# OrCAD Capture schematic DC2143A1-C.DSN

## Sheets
1 PAGE1: size C
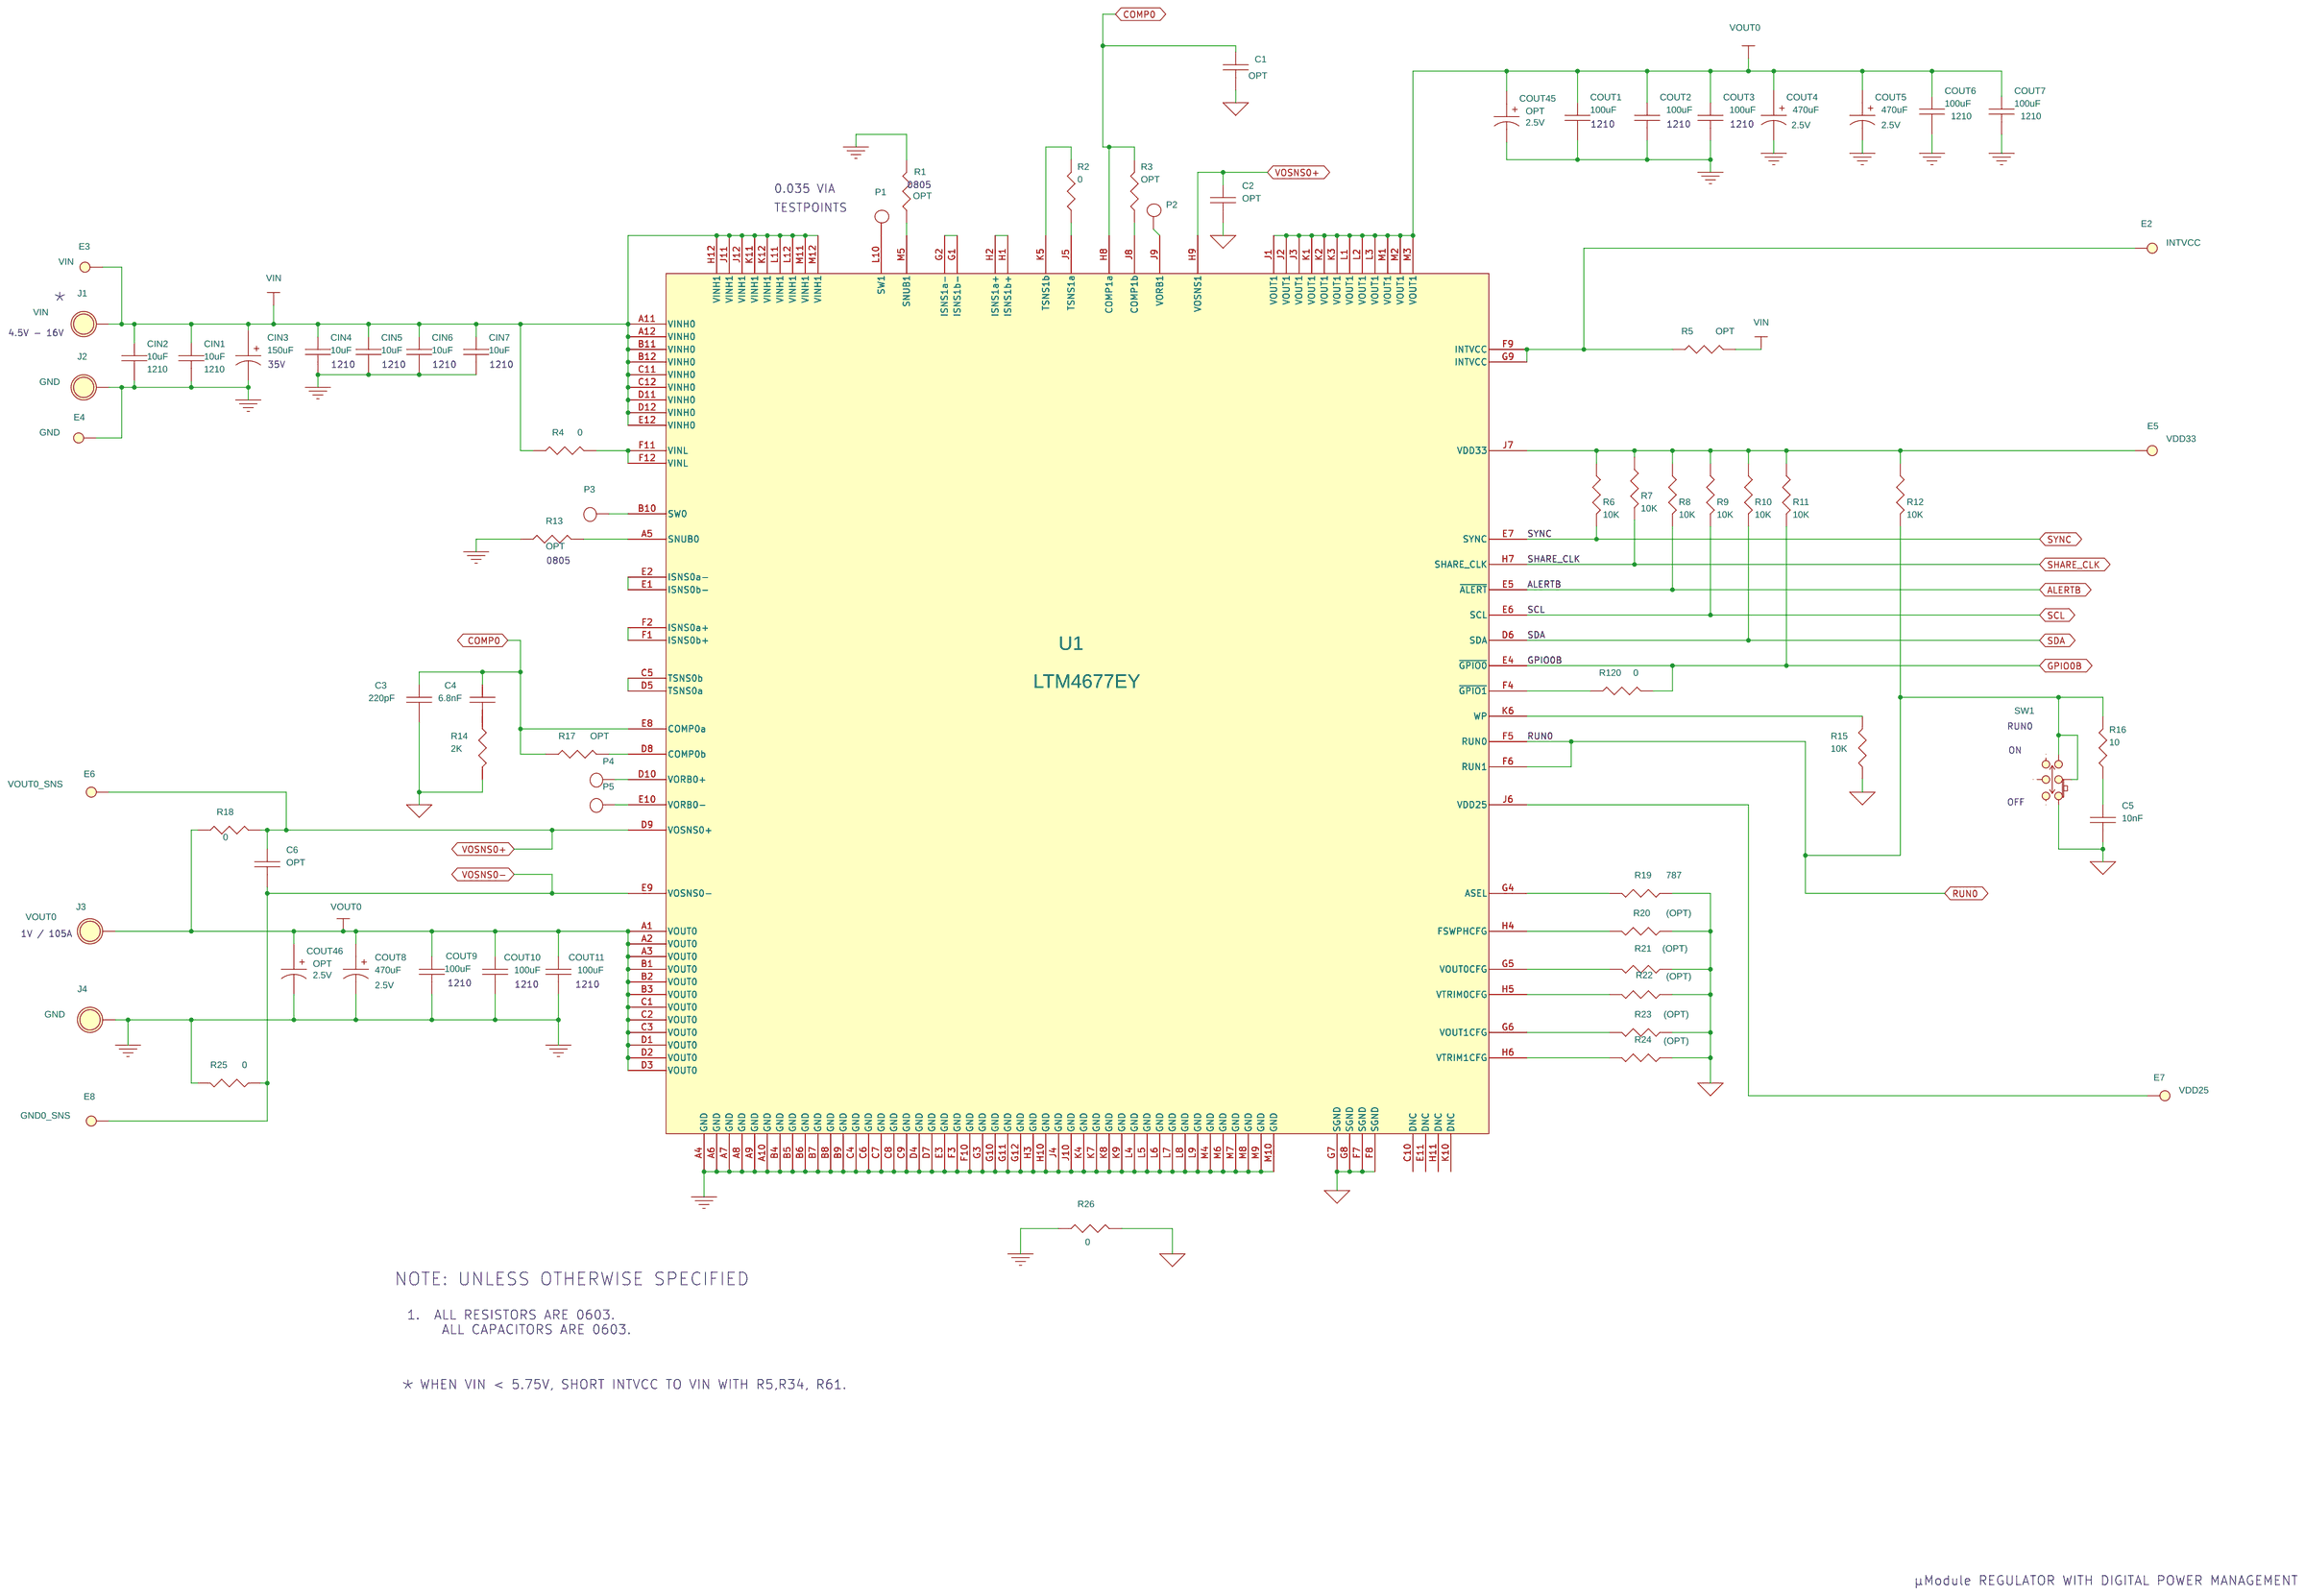
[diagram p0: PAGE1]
2 PAGE2: size C; title: HIGH EFFICIENCY, POLY-PHASE, DC/DC STEP-DOWN; rev: 1; company: TM
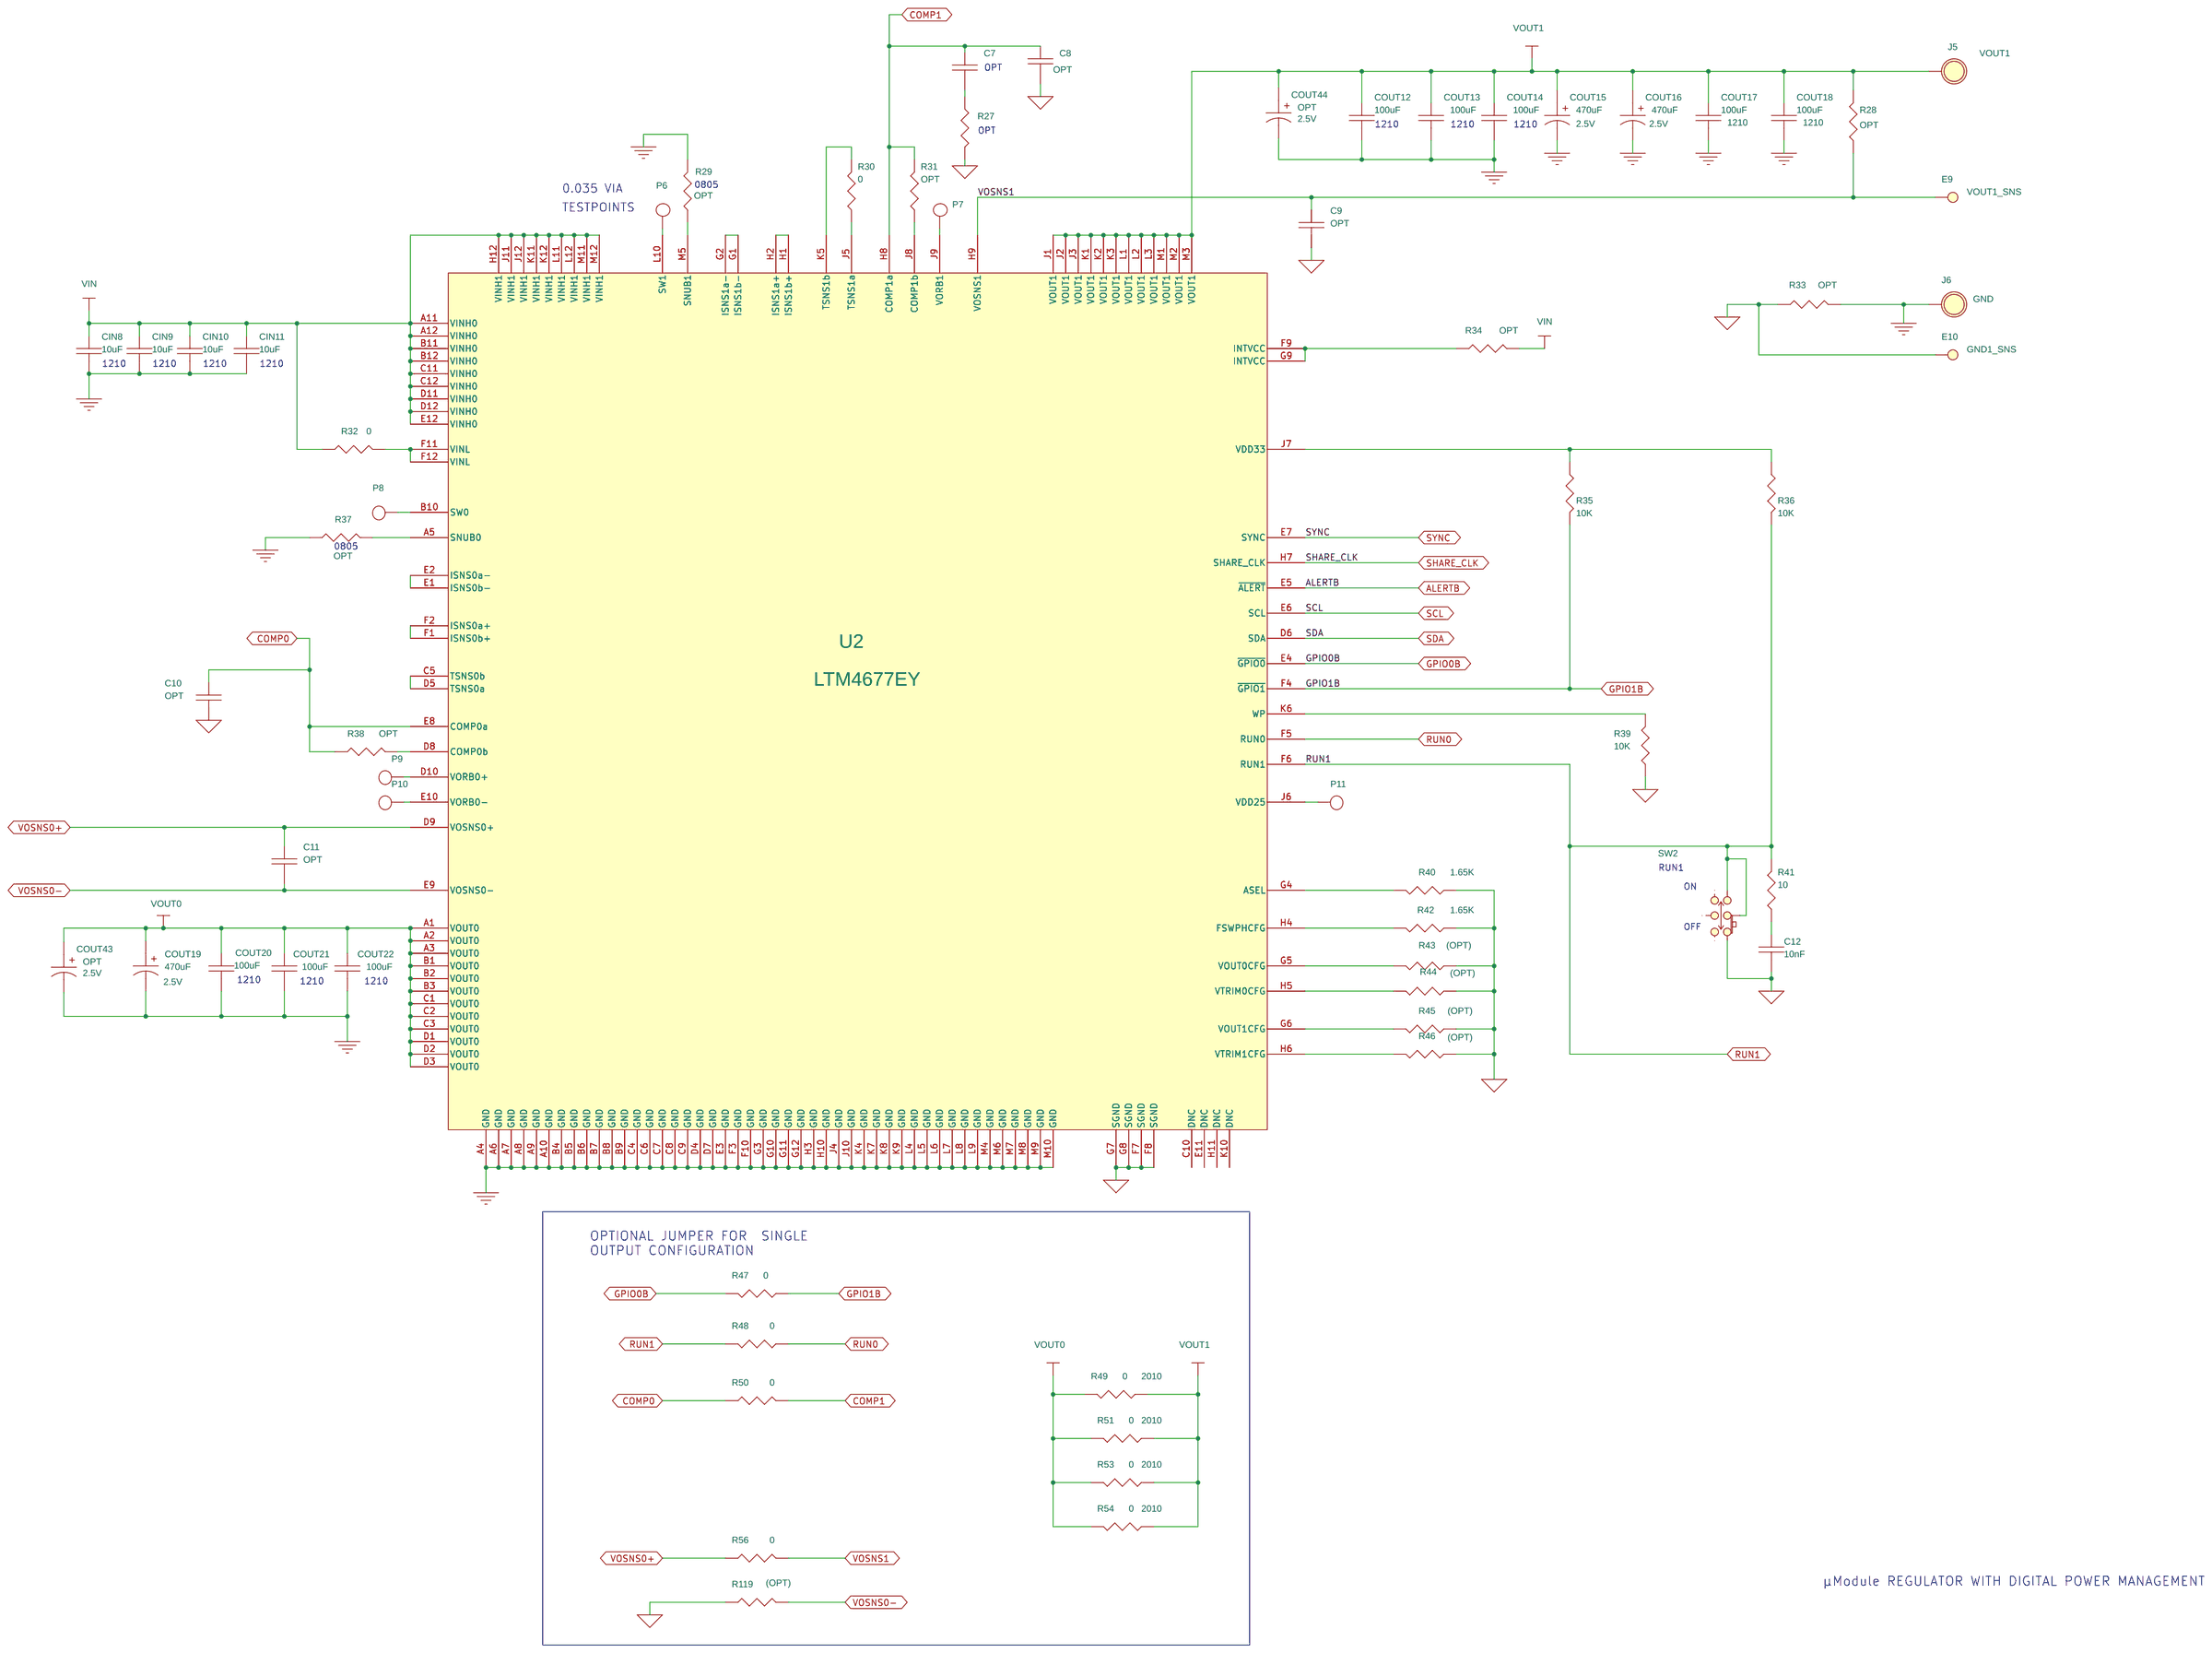
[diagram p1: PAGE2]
3 PAGE3: size C; title: HIGH EFFICIENCY, POLY-PHASE, DC/DC STEP-DOWN; rev: 1; company: TM
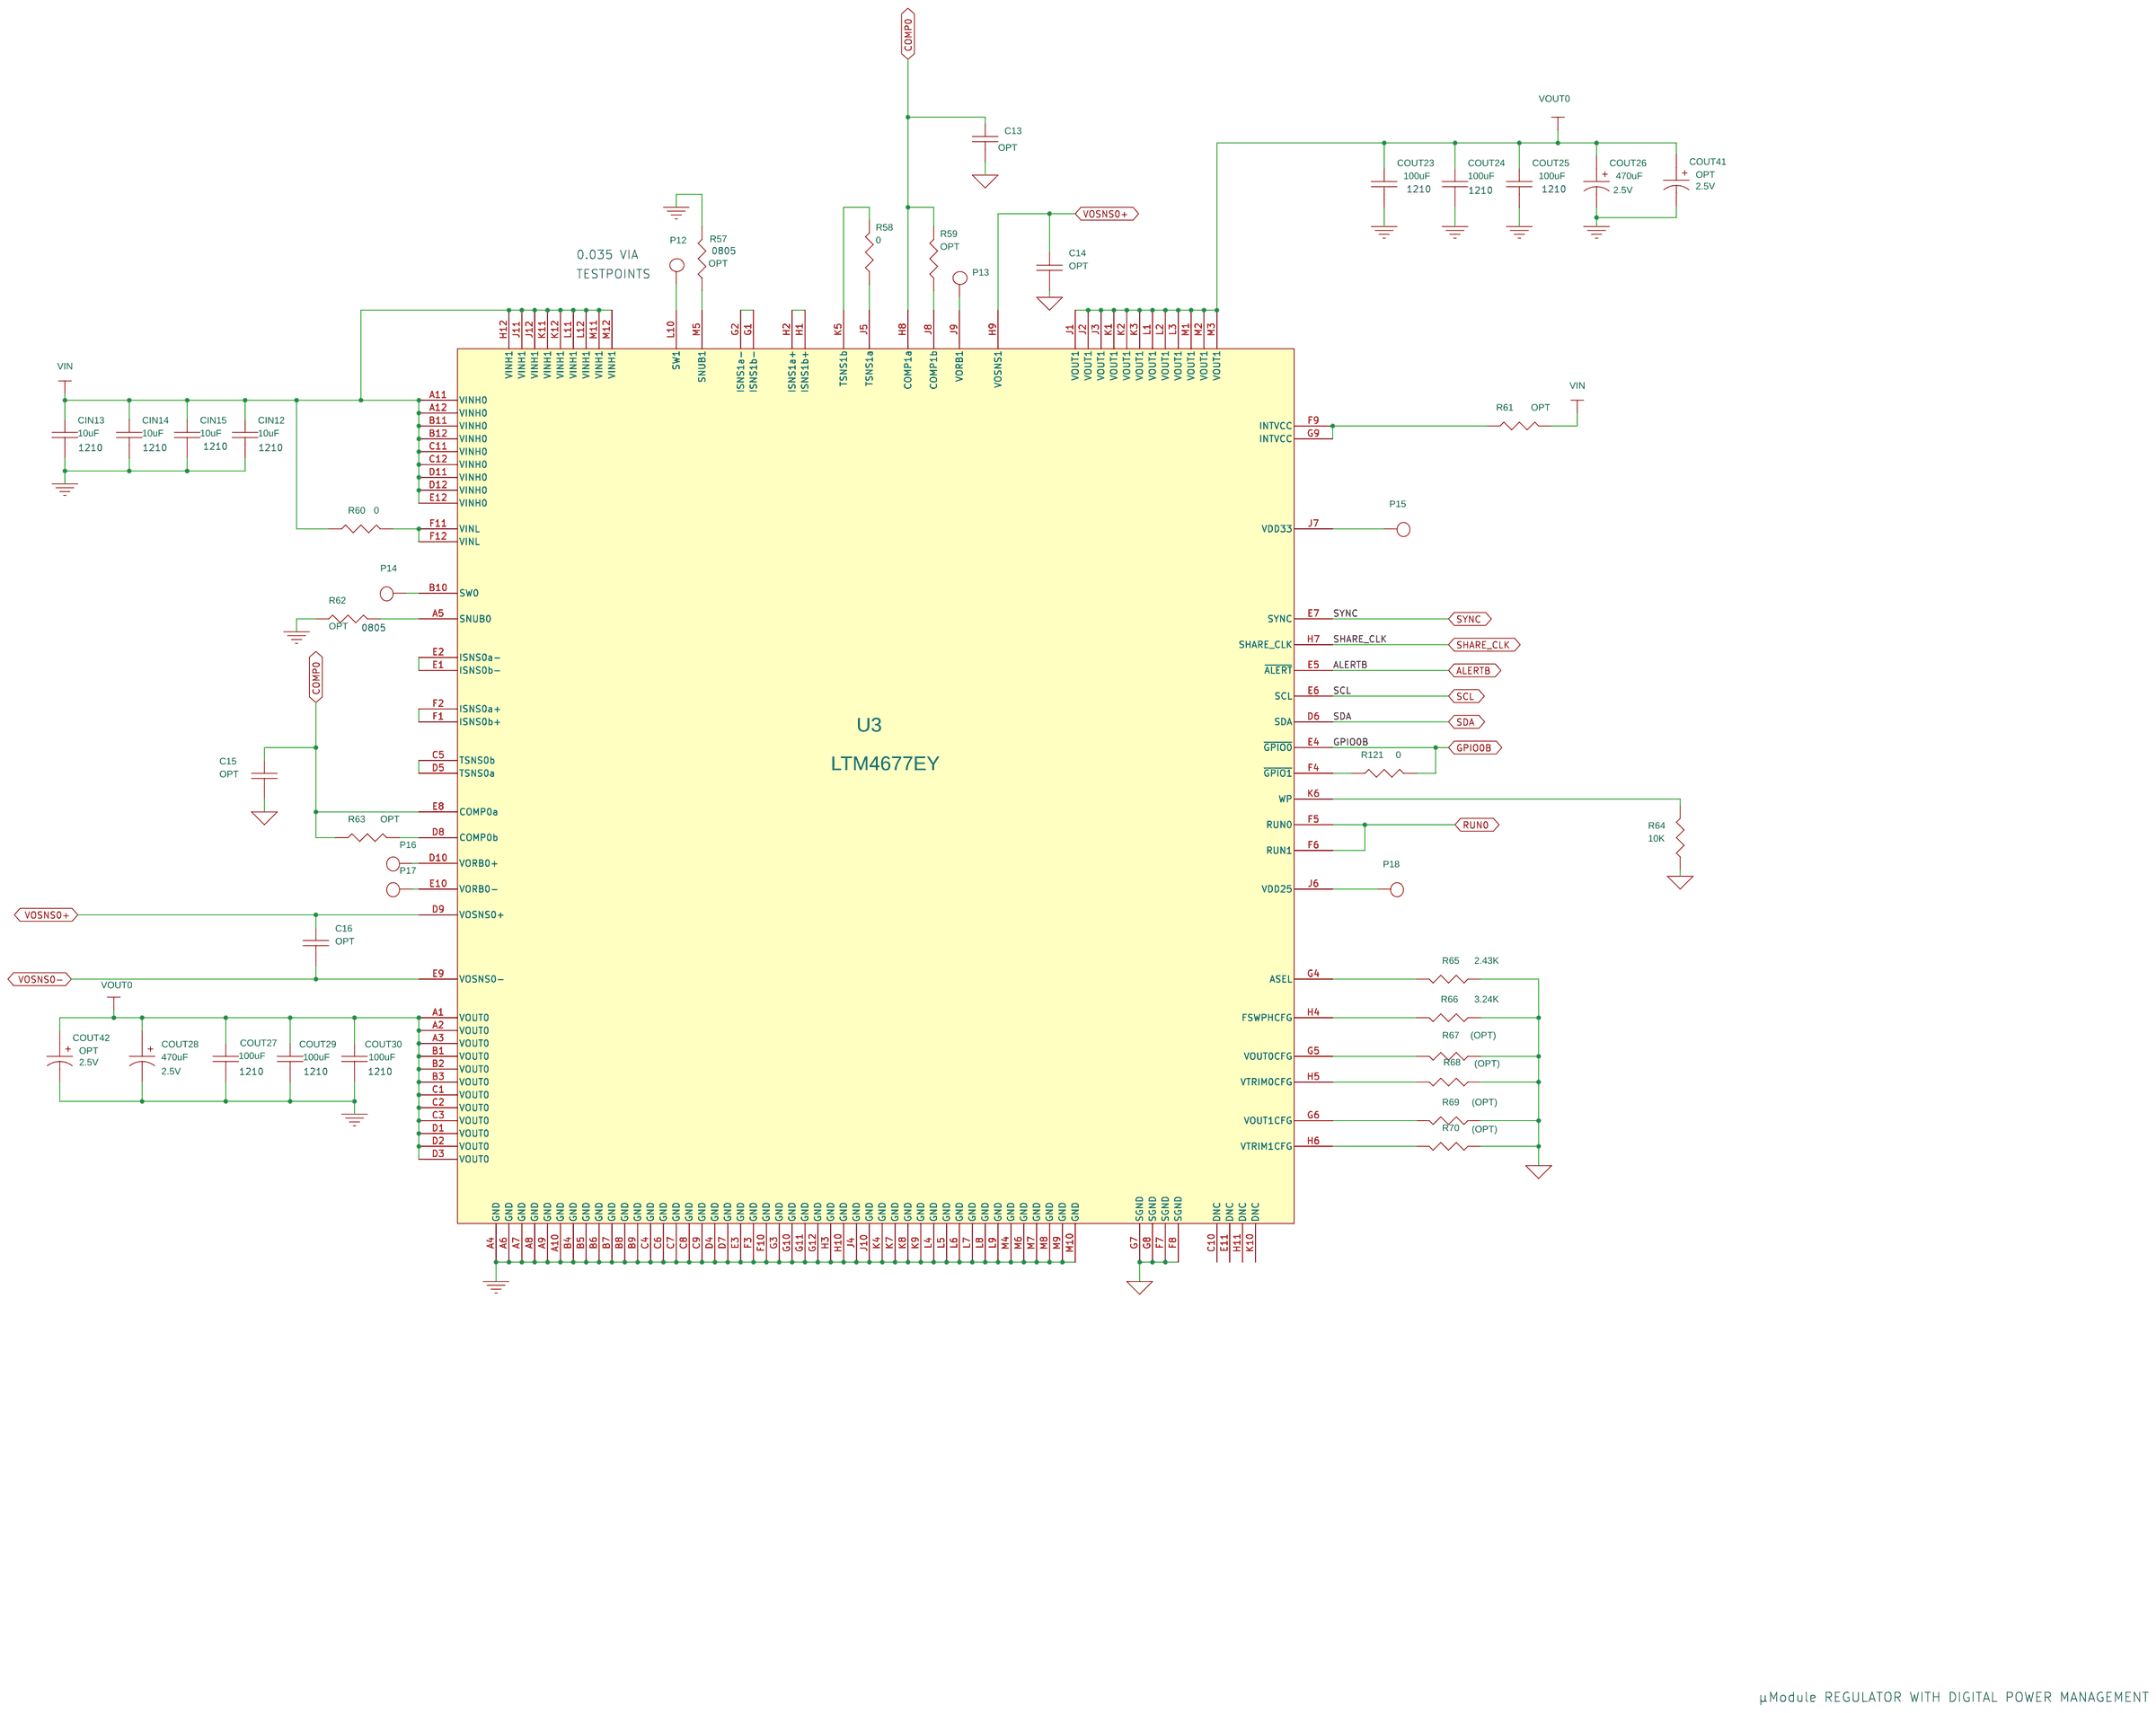
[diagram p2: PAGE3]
4 PAGE4: size C; title: HIGH EFFICIENCY, POLY-PHASE, DC/DC STEP-DOWN; rev: 1; company: TM
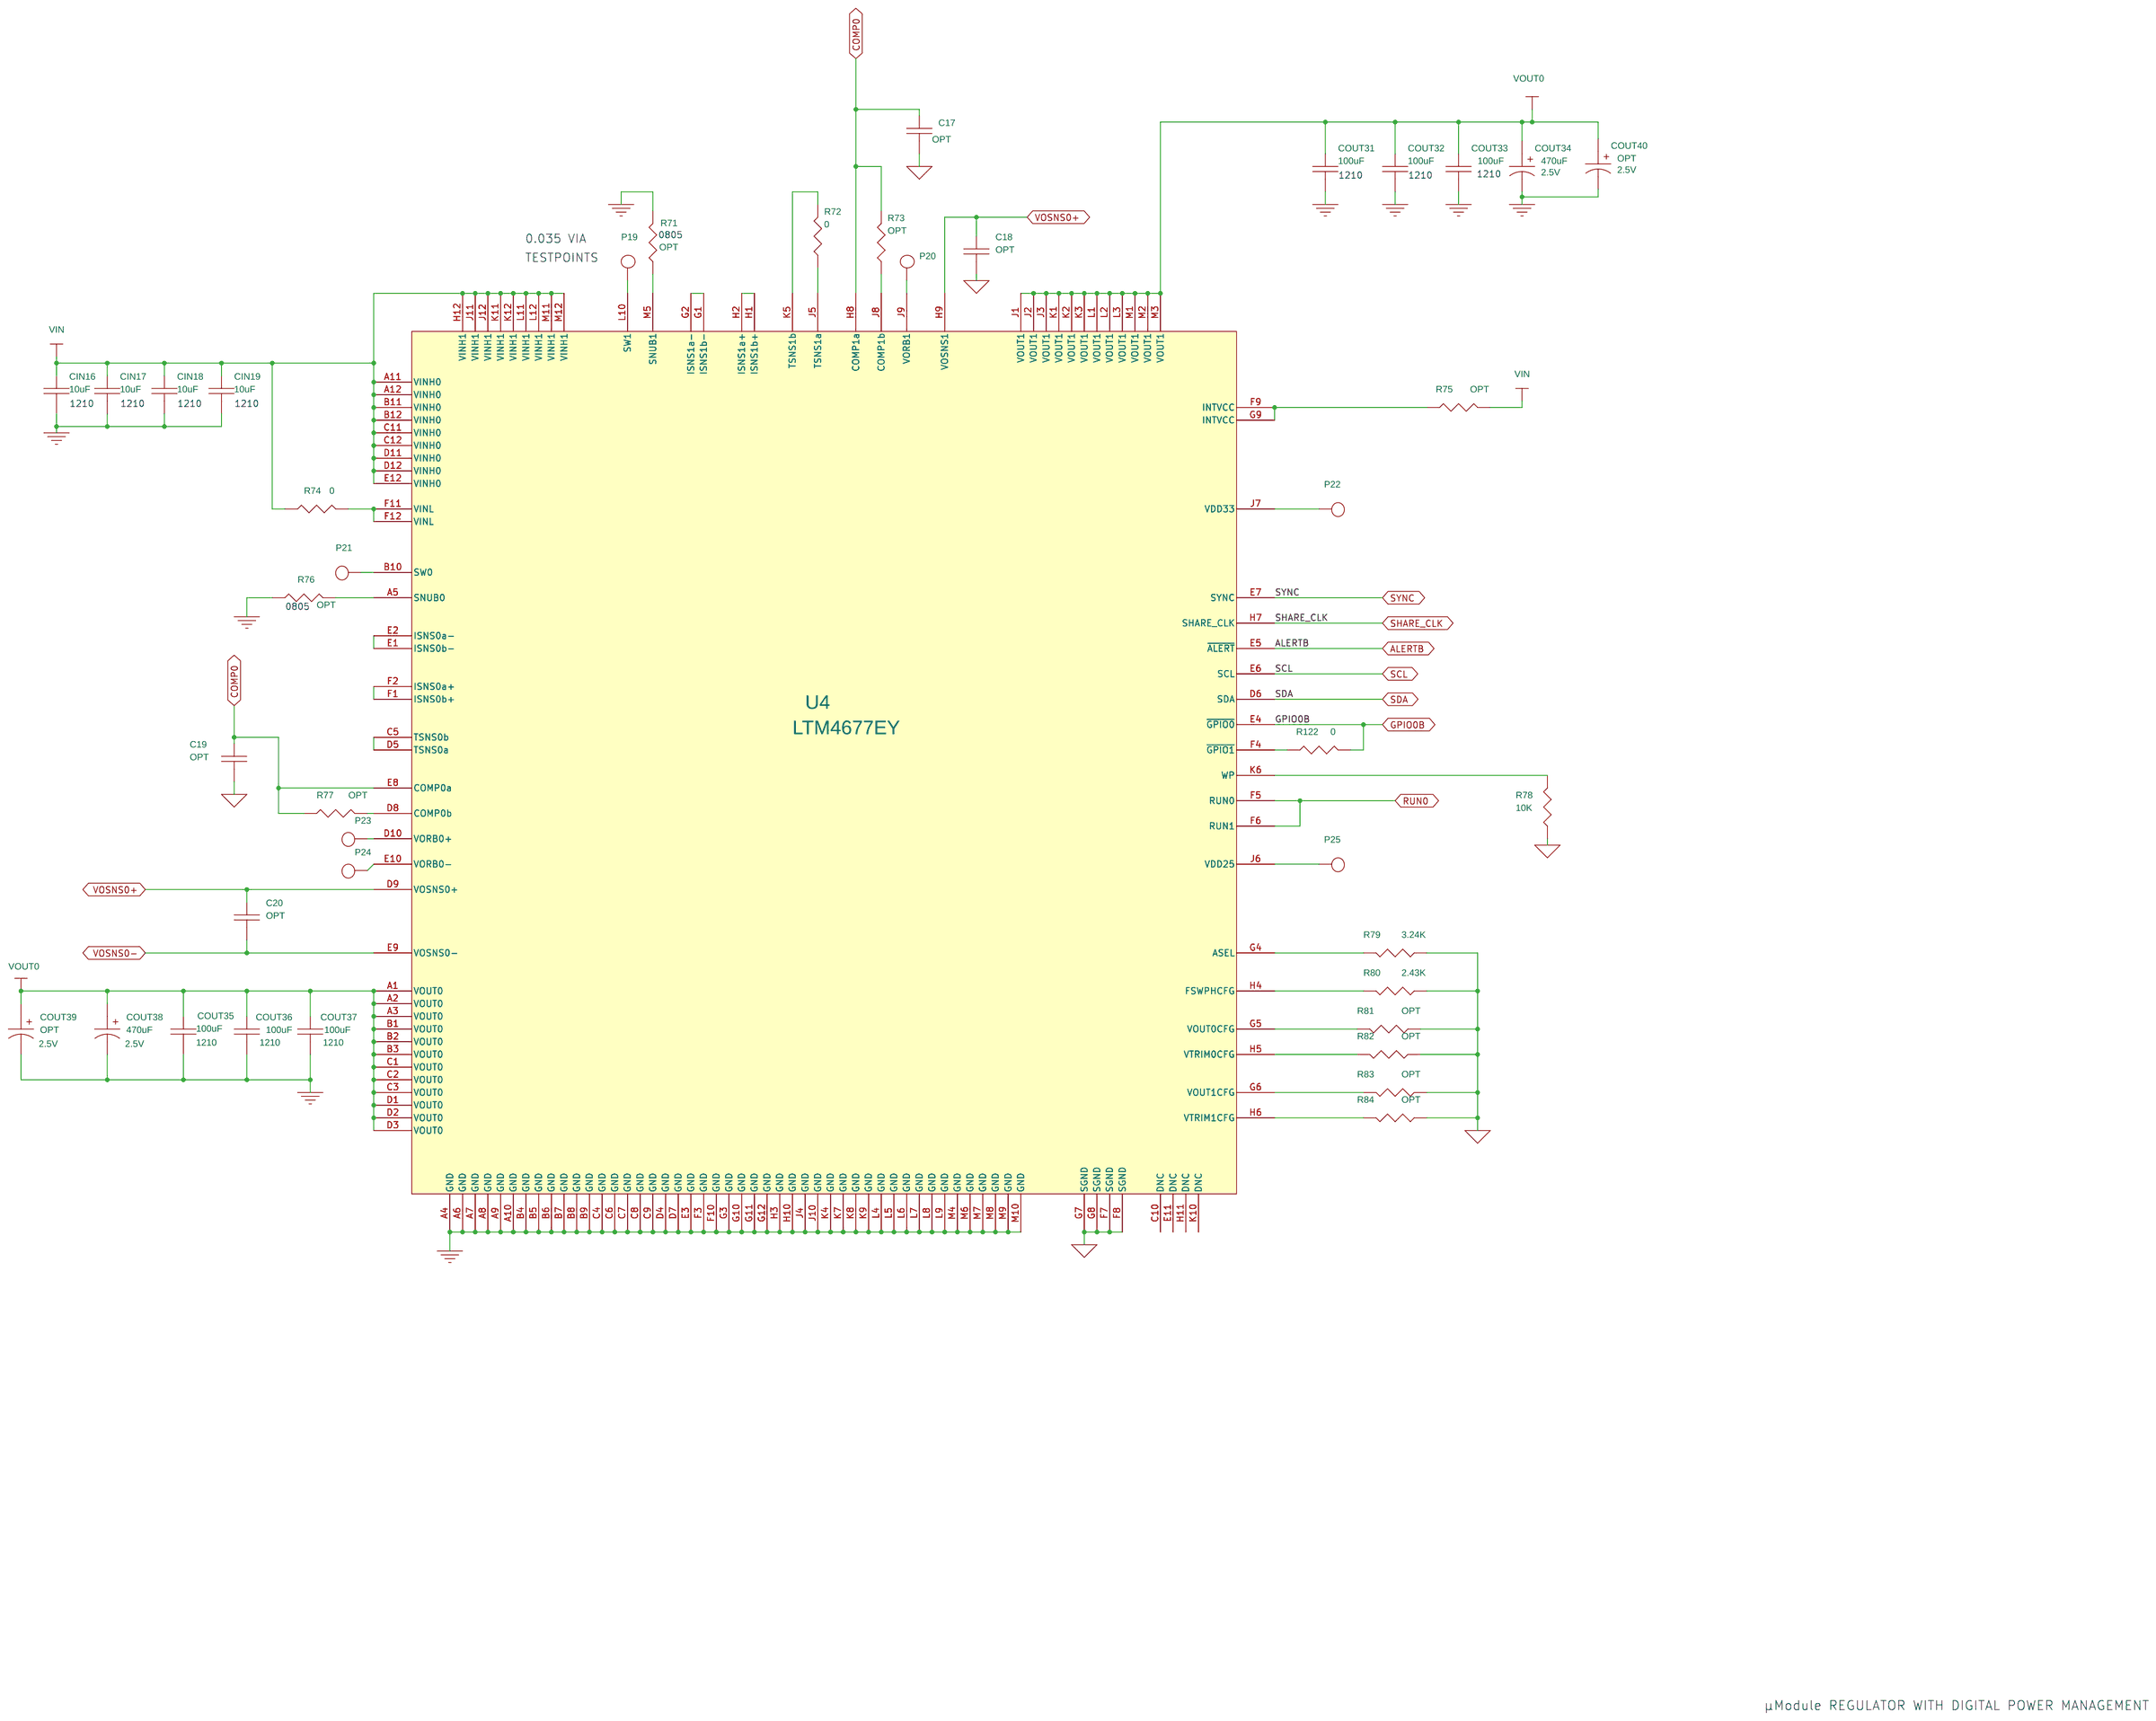
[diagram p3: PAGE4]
5 PAGE5: size C; title: HIGH EFFICIENCY, POLY-PHASE, DC/DC STEP-DOWN; rev: 1; company: TM
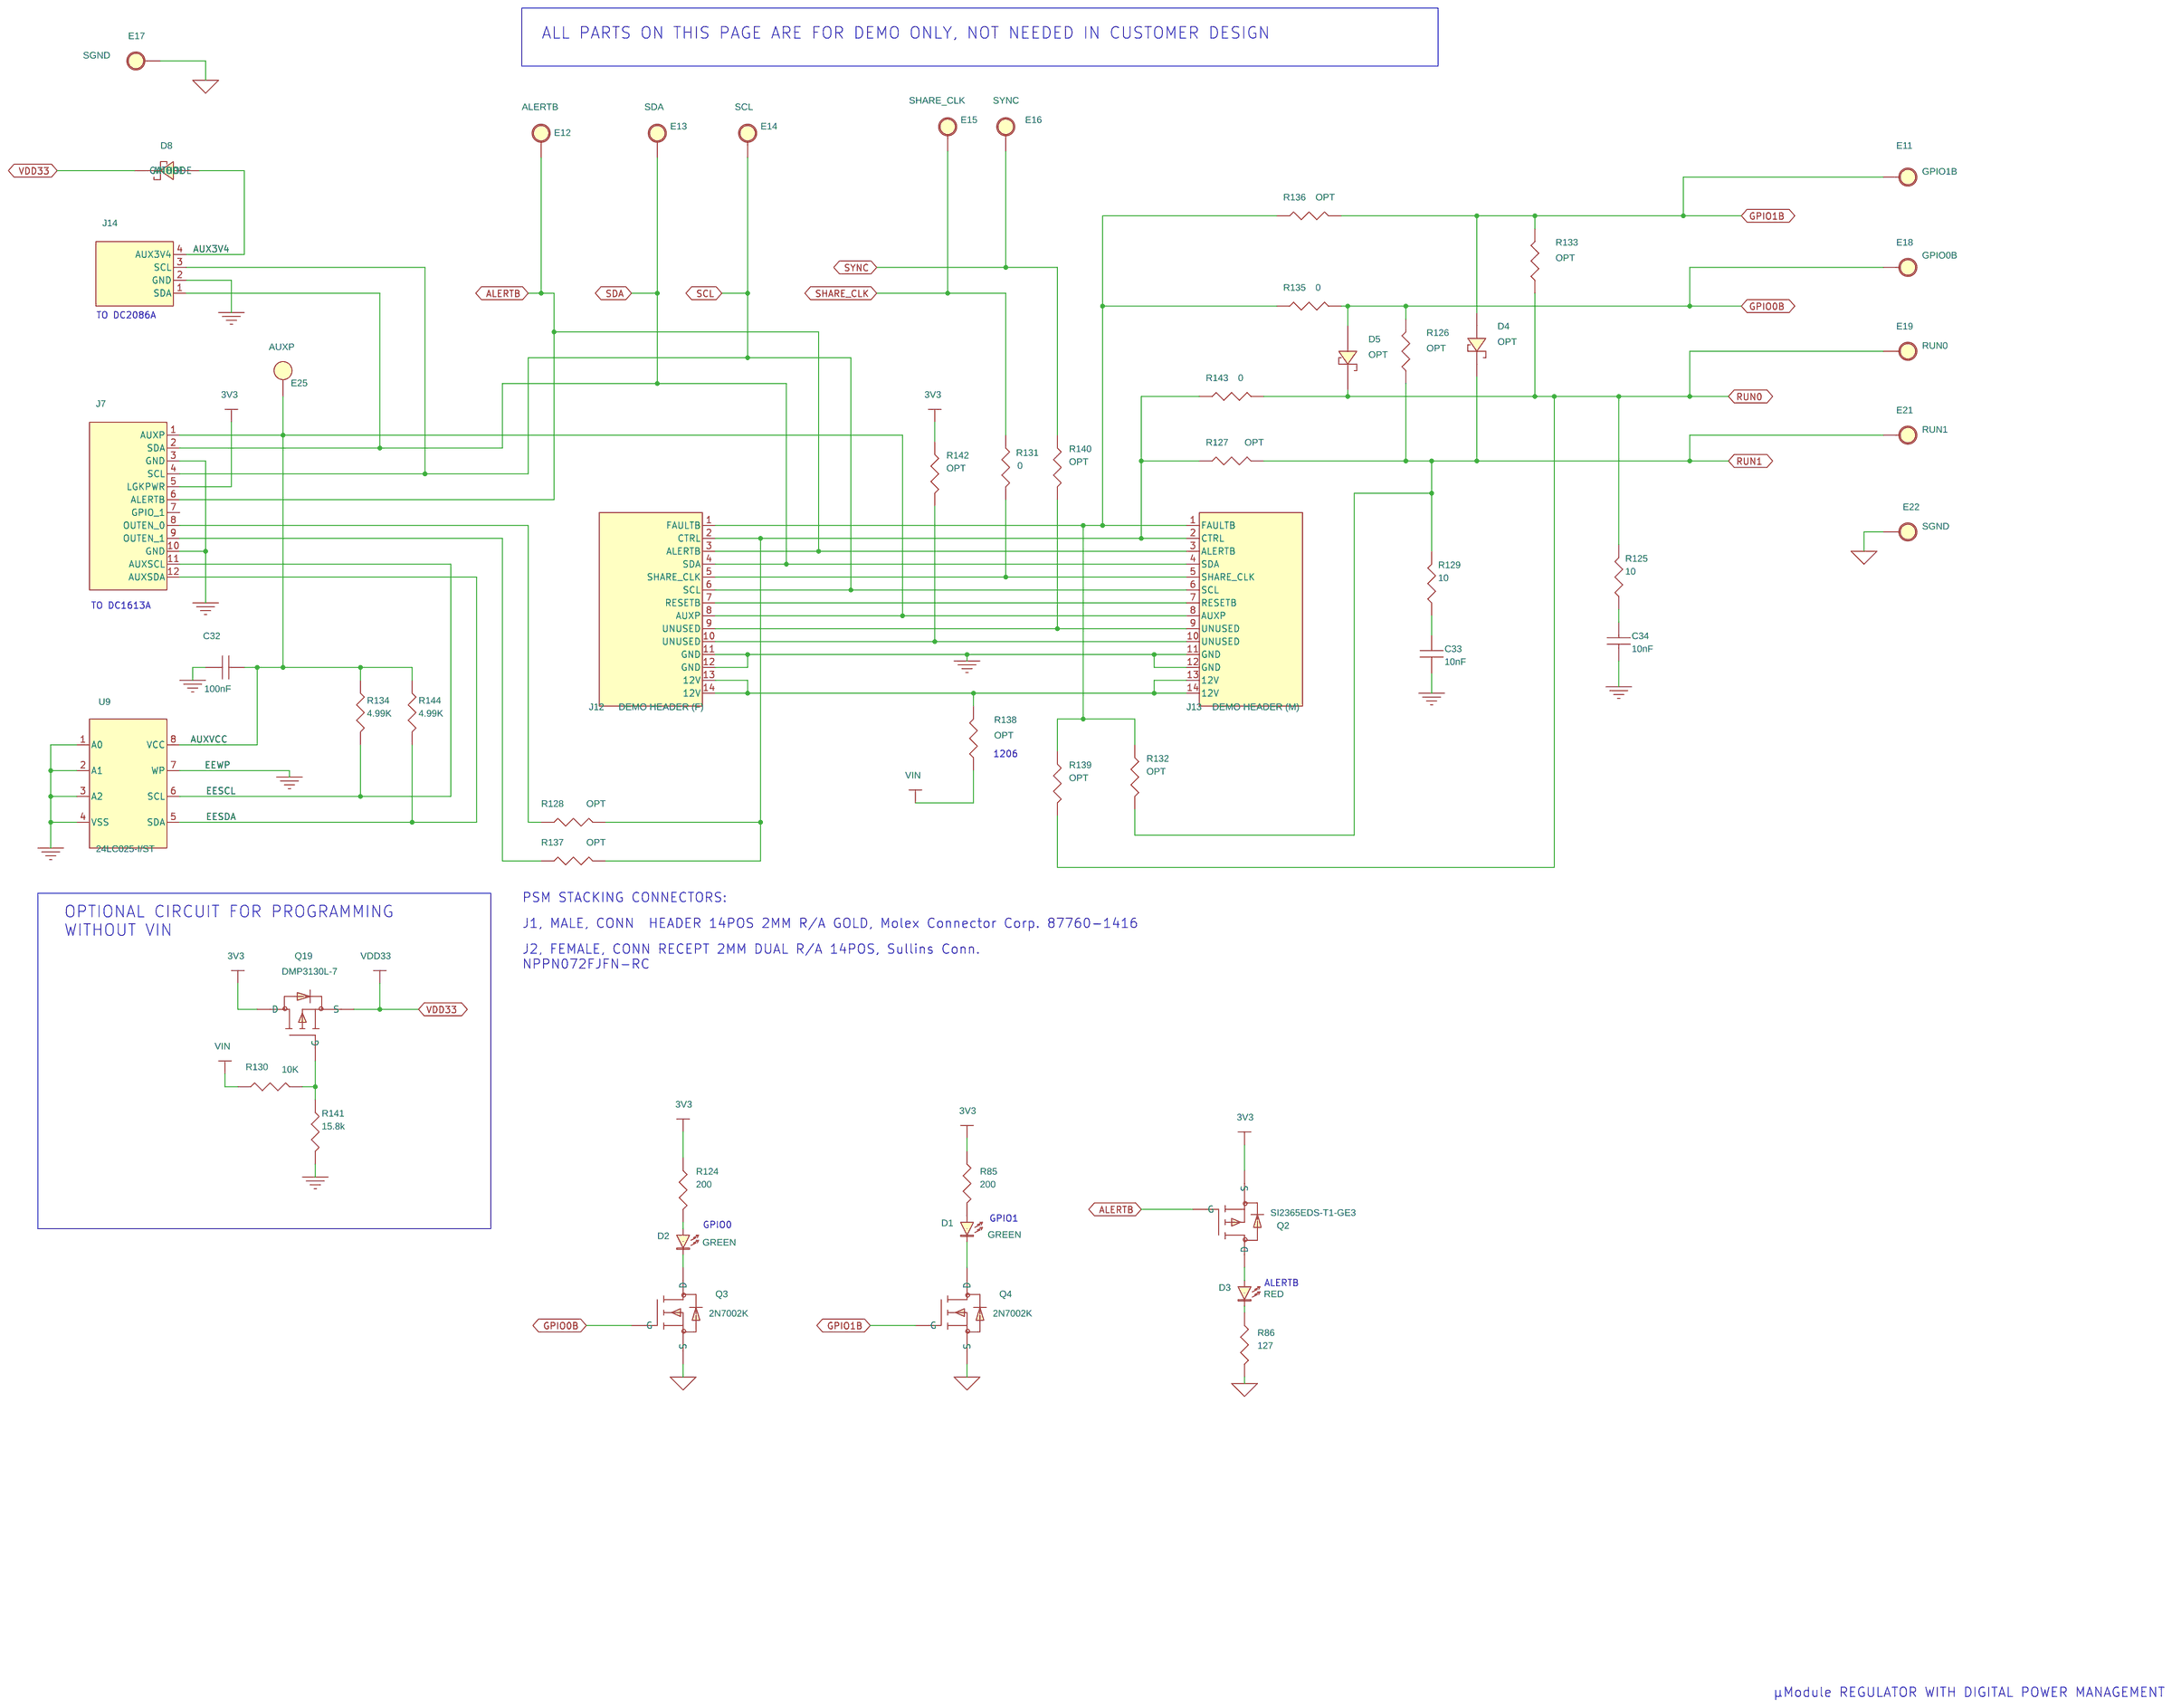
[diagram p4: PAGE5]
6 PAGE6: size B; title: HIGH EFFICIENCY, POLY-PHASE, DC/DC STEP-DOWN; rev: 1; company: TM
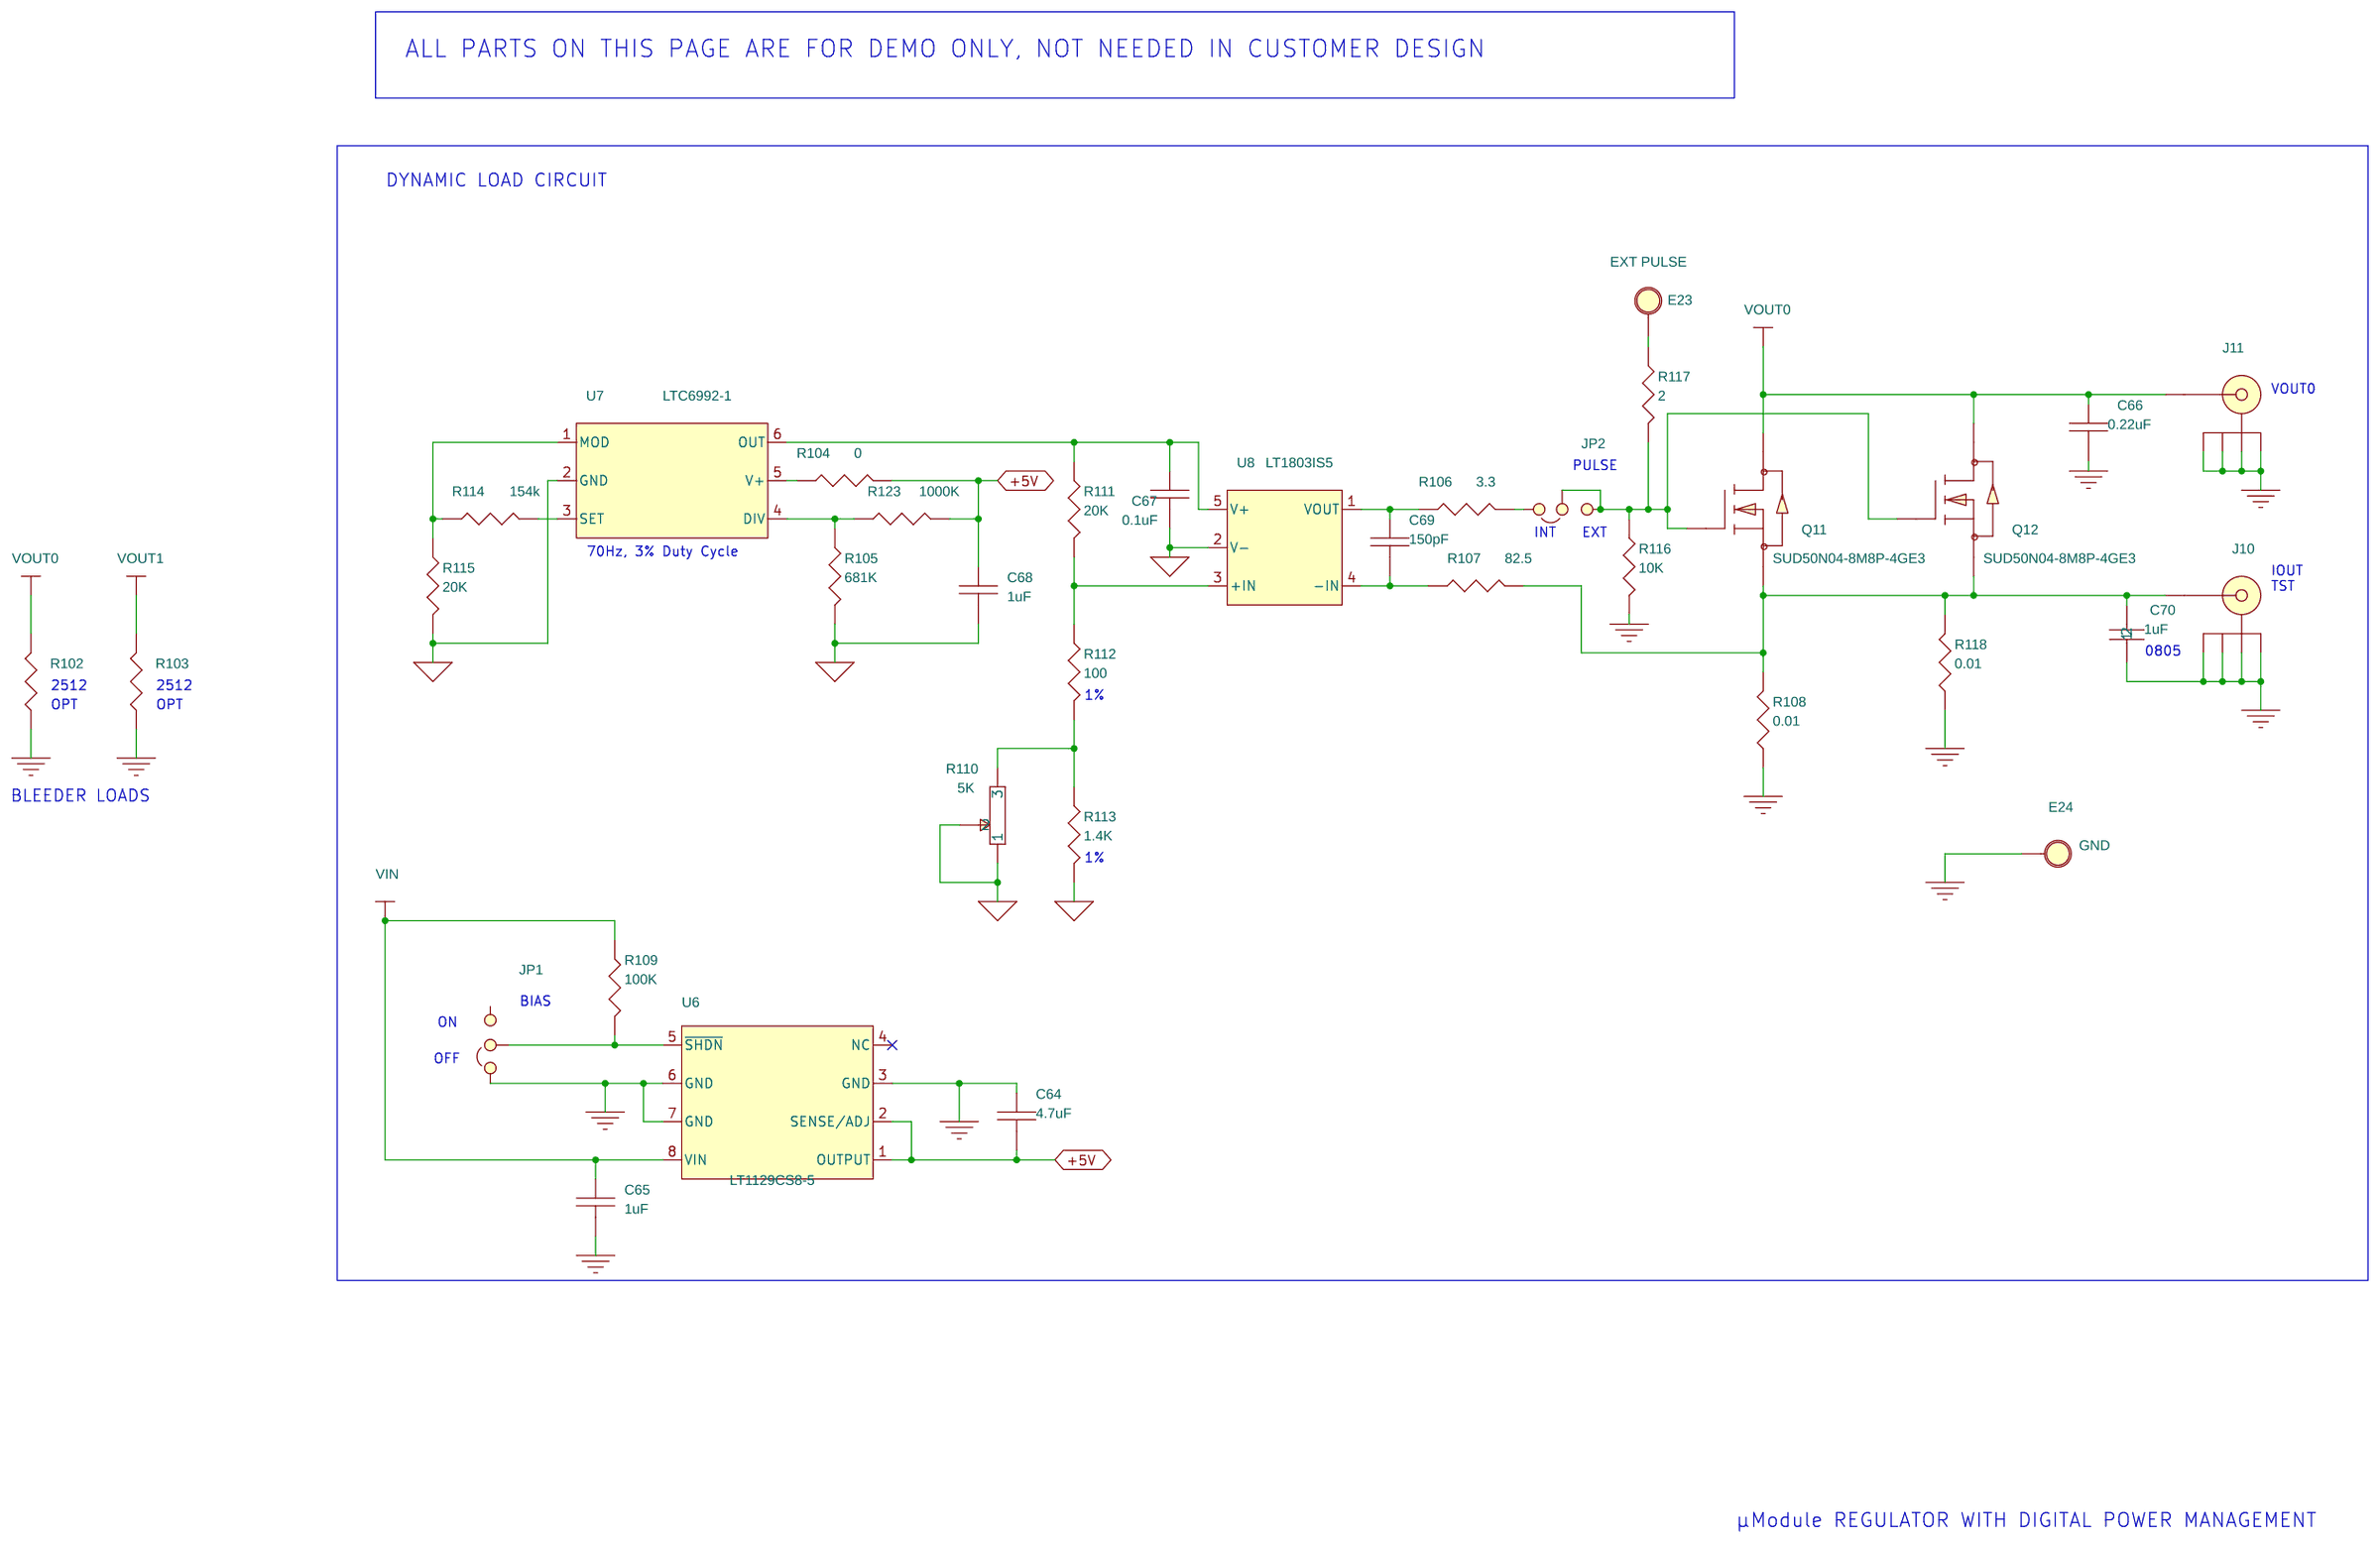
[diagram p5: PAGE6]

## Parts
sheet PAGE1
C1  OPT  [0603]
C2  OPT  [0603]
C3  220pF  [0603]
C4  6.8nF  [0603]
C5  10nF  [0603]
C6  OPT  [0603]
CIN1  10uF  [1210]
CIN2  10uF  [1210]
CIN3  150uF  [SANYO\8X10]
CIN4  10uF  [1210]
CIN5  10uF  [1210]
CIN6  10uF  [1210]
CIN7  10uF  [1210]
COUT1  100uF  [1210]
COUT2  100uF  [1210]
COUT3  100uF  [1210]
COUT4  470uF  [D3L]
COUT5  470uF  [D3L]
COUT6  100uF  [1210]
COUT7  100uF  [1210]
COUT8  470uF  [D3L]
COUT9  100uF  [1210]
COUT10  100uF  [1210]
COUT11  100uF  [1210]
COUT45  OPT  [D3L]
COUT46  OPT  [D3L]
E2  INTVCC  [TURRETS]
E3  TURRETS  [TURRETS]
E4  GND  [TURRETS]
E5  VDD33  [TURRETS]
E6  TURRETS  [TURRETS]
E7  VDD25  [TURRETS]
E8  TURRETS  [TURRETS]
J1  BANANA SMALL  [CON\LUG\10]
J2  BANANA SMALL  [CON\LUG\10]
J3  BANANA SMALL  [CON\LUG\10]
J4  BANANA SMALL  [CON\LUG\10]
P1  TURRETS  [PAD]
P2  TURRETS  [PAD]
P3  TURRETS  [PAD]
P4  TURRETS  [PAD]
P5  TURRETS  [PAD]
R1  OPT  [0805]
R2  0  [0603]
R3  OPT  [0603]
R4  0  [0603]
R5  OPT  [0603]
R6  10K  [0603]
R7  10K  [0603]
R8  10K  [0603]
R9  10K  [0603]
R10  10K  [0603]
R11  10K  [0603]
R12  10K  [0603]
R13  OPT  [0805]
R14  2K  [0603]
R15  10K  [0603]
R16  10  [0603]
R17  OPT  [0603]
R18  0  [0603]
R19  787  [0603]
R20  (OPT)  [0603]
R21  (OPT)  [0603]
R22  (OPT)  [0603]
R23  (OPT)  [0603]
R24  (OPT)  [0603]
R25  0  [0603]
R26  0  [0603]
R120  0  [0603]
SW1  JP3X1/079\NO\12  [JS202011]
U1  LTM4677EY  [a]
sheet PAGE2
C7  470pF  [0603]
C8  OPT  [0603]
C9  OPT  [0603]
C10  OPT  [0603]
C11  OPT  [0603]
C12  10nF  [0603]
CIN8  10uF  [1210]
CIN9  10uF  [1210]
CIN10  10uF  [1210]
CIN11  10uF  [1210]
COUT12  100uF  [1210]
COUT13  100uF  [1210]
COUT14  100uF  [1210]
COUT15  470uF  [D3L]
COUT16  470uF  [D3L]
COUT17  100uF  [1210]
COUT18  100uF  [1210]
COUT19  470uF  [D3L]
COUT20  100uF  [1210]
COUT21  100uF  [1210]
COUT22  100uF  [1210]
COUT43  OPT  [D3L]
COUT44  OPT  [D3L]
E9  TURRETS  [TURRETS]
E10  TURRETS  [TURRETS]
J5  BANANA SMALL  [KEY-575-4]
J6  BANANA SMALL  [KEY-575-4]
P6  TURRETS  [PAD]
P7  TURRETS  [PAD]
P8  TURRETS  [PAD]
P9  TURRETS  [PAD]
P10  TURRETS  [PAD]
P11  TURRETS  [PAD]
R27  51K  [0603]
R28  OPT  [0603]
R29  OPT  [0805]
R30  0  [0603]
R31  OPT  [0603]
R32  0  [0603]
R33  OPT  [0603]
R34  OPT  [0603]
R35  10K  [0603]
R36  10K  [0603]
R37  OPT  [0805]
R38  OPT  [0603]
R39  10K  [0603]
R40  1.65K  [0603]
R41  10  [0603]
R42  1.65K  [0603]
R43  (OPT)  [0603]
R44  (OPT)  [0603]
R45  (OPT)  [0603]
R46  (OPT)  [0603]
R47  0  [0603]
R48  0  [0603]
R49  0  [2010]
R50  0  [0603]
R51  0  [2010]
R53  0  [2010]
R54  0  [2010]
R56  0  [0603]
R119  (OPT)  [0603]
SW2  JP3X1/079\NO\12  [JS202011]
U2  LTM4677EY  [a]
sheet PAGE3
C13  OPT  [0603]
C14  OPT  [0603]
C15  OPT  [0603]
C16  OPT  [0603]
CIN12  10uF  [1210]
CIN13  10uF  [1210]
CIN14  10uF  [1210]
CIN15  10uF  [1210]
COUT23  100uF  [1210]
COUT24  100uF  [1210]
COUT25  100uF  [1210]
COUT26  470uF  [D3L]
COUT27  100uF  [1210]
COUT28  470uF  [D3L]
COUT29  100uF  [1210]
COUT30  100uF  [1210]
COUT41  OPT  [D3L]
COUT42  OPT  [D3L]
P12  TURRETS  [PAD]
P13  TURRETS  [PAD]
P14  TURRETS  [PAD]
P15  TURRETS  [PAD]
P16  TURRETS  [PAD]
P17  TURRETS  [PAD]
P18  TURRETS  [PAD]
R57  OPT  [0805]
R58  0  [0603]
R59  OPT  [0603]
R60  0  [0603]
R61  OPT  [0603]
R62  OPT  [0805]
R63  OPT  [0603]
R64  10K  [0603]
R65  2.43K  [0603]
R66  3.24K  [0603]
R67  (OPT)  [0603]
R68  (OPT)  [0603]
R69  (OPT)  [0603]
R70  (OPT)  [0603]
R121  0  [0603]
U3  LTM4677EY  [a]
sheet PAGE4
C17  OPT  [0603]
C18  OPT  [0603]
C19  OPT  [0603]
C20  OPT  [0603]
CIN16  10uF  [1210]
CIN17  10uF  [1210]
CIN18  10uF  [1210]
CIN19  10uF  [1210]
COUT31  100uF  [1210]
COUT32  100uF  [1210]
COUT33  100uF  [1210]
COUT34  470uF  [D3L]
COUT35  100uF  [1210]
COUT36  100uF  [1210]
COUT37  100uF  [1210]
COUT38  470uF  [D3L]
COUT39  OPT  [D3L]
COUT40  OPT  [D3L]
P19  TURRETS  [PAD]
P20  TURRETS  [PAD]
P21  TURRETS  [PAD]
P22  TURRETS  [PAD]
P23  TURRETS  [PAD]
P24  TURRETS  [PAD]
P25  TURRETS  [PAD]
R71  OPT  [0805]
R72  0  [0603]
R73  OPT  [0603]
R74  0  [0603]
R75  OPT  [0603]
R76  OPT  [0805]
R77  OPT  [0603]
R78  10K  [0603]
R79  3.24K  [0603]
R80  2.43K  [0603]
R81  OPT  [0603]
R82  OPT  [0603]
R83  OPT  [0603]
R84  OPT  [0603]
R122  0  [0603]
U4  LTM4677EY  [a]
sheet PAGE5
C32  100nF  [0603]
C33  10nF  [0603]
C34  10nF  [0603]
D1  GREEN  [led]
D2  GREEN  [led]
D3  RED  [led]
D4  OPT  [SOD323]
D5  OPT  [SOD323]
D8  DIODE SCHOTTKY  [PMEG2005AEL]
E11  TURRETS  [TURRETS]
E12  TURRETS  [TURRETS]
E13  TURRETS  [TURRETS]
E14  TURRETS  [TURRETS]
E15  TURRETS  [TURRETS]
E16  TURRETS  [TURRETS]
E17  SGND  [TURRETS]
E18  TURRETS  [TURRETS]
E19  TURRETS  [TURRETS]
E21  TURRETS  [TURRETS]
E22  SGND  [TURRETS]
E25  AUXP  [TURRETS]
J7  HD2X6-079  [HD2X6-079-MOLEX]
J12  DEMO HEADER (F)  [NPPN072FJFN-RC]
J13  DEMO HEADER (M)  [NPPN072FJFN]
J14  HD2X6-079-PMBUS_0  [DF3A-4P-2DSA]
Q2  SI2365EDS-T1-GE3  [SOT-23]
Q3  2N7002K  [SOT-23]
Q4  2N7002K  [SOT-23]
Q19  DMP3130L-7  [SOT-23]
R85  200  [0603]
R86  127  [0603]
R124  200  [0603]
R125  10  [0603]
R126  OPT  [0603]
R127  OPT  [0603]
R128  OPT  [0603]
R129  10  [0603]
R130  10K  [0603]
R131  0  [0603]
R132  OPT  [0603]
R133  OPT  [0603]
R134  4.99K  [0603]
R135  0  [0603]
R136  OPT  [0603]
R137  OPT  [0603]
R138  OPT  [1206]
R139  OPT  [0603]
R140  OPT  [0603]
R141  15.8k  [0603]
R142  OPT  [0603]
R143  0  [0603]
R144  4.99K  [0603]
U9  24LC025-I/ST  [TSSOP-8_4.4MM]
sheet PAGE6
C64  4.7uF  [0603]
C65  1uF  [1206]
C66  0.22uF  [0805]
C67  0.1uF  [1206]
C68  1uF  [1206]
C69  150pF  [0603]
C70  1uF  [0805]
E23  TURRETS  [TURRETS]
E24  TURRETS  [TURRETS]
J10  XXX  [BNC]
J11  XXX  [BNC]
JP1  JP3X1/079\NO\12  [HD1X3-079]
JP2  JP3X1/079\NO\12  [HD1X3-079]
Q11  SUD50N04-8M8P-4GE3  [TO-252]
Q12  SUD50N04-8M8P-4GE3  [TO-252]
R102  OPT  [2512SENSE]
R103  OPT  [2512SENSE]
R104  0  [0603]
R105  681K  [0603]
R106  3.3  [0603]
R107  82.5  [0603]
R108  0.01  [2010]
R109  100K  [0603]
R110  5K  [POTENTIOMETER/3386]
R111  20K  [0603]
R112  100  [0603]
R113  1.4K  [0603]
R114  154k  [0603]
R115  20K  [0603]
R116  10K  [0603]
R117  2  [0603]
R118  0.01  [2010]
R123  1000K  [0603]
U6  LT1129CS8-5  [SO8NB]
U7  LTC6992-1  [S6-TSOT23]
U8  LT1803IS5  [S5-TSOT23]

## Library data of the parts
C1-C4 C6-C11 C13-C20 = CAP0603_1: Component: cap; Manufacturer: TDK; Manufacturer P/N: C1608C0G1H102J; Tolerance: 5%; Type: cer 0603; Vendor: Digikey; Vendor P/N: 445-1293-1-ND; Volts/Amps/Watts: 50V
C5 C12 C69 = CAP0603_2: Component: cap; Manufacturer: TDK; Manufacturer P/N: C1608C0G1H102J; Tolerance: 5%; Type: cer 0603; Vendor: Digikey
CIN1 CIN2 CIN4-CIN19 = CAP1210_1: Component: cap; Manufacturer: Taiyo Yuden; Manufacturer P/N: GMK325BJ106KN-T; Tolerance: 10%; Type: cer 1210; Vendor: Digikey; Vendor P/N: 587-1439-1-ND; Volts/Amps/Watts: 35V
CIN3 = CAPR12X5_0: Component: cap; Manufacturer: SANYO; Tolerance: 20%; Type: OS-CON; Volts/Amps/Watts: 16V
COUT1 COUT12 COUT23 COUT31 = CAP0603_1: Component: cap; Manufacturer: TDK; Manufacturer P/N: C3225X5R0J107M; Tolerance: 20%; Type: cer 1210 X5R; Vendor: Digikey; Vendor P/N: 445-1437-1-ND; Volts/Amps/Watts: 6.3v
COUT2 COUT3 COUT6 COUT7 COUT9-COUT11 COUT13 COUT14 COUT17 COUT18 COUT20-COUT22 COUT25 COUT27 COUT29 COUT30 COUT32 COUT33 COUT35-COUT37 = CAP0603_1: Component: cap; Manufacturer: TDK; Manufacturer P/N: C3225X5R0J107M; Part Type: CAP1210; Tolerance: 20%; Type: cer 1210 X5R; Vendor: Digikey; Vendor P/N: 445-1437-1-ND; Volts/Amps/Watts: 6.3v
COUT4 COUT5 COUT8 COUT15 COUT16 COUT19 COUT26 COUT28 COUT34 COUT38-COUT46 = CAPR12X5_0: Component: cap; Manufacturer: SANYO; Manufacturer P/N: 2R5TPE470M7; Tolerance: 20%; Type: TANT; Volts/Amps/Watts: 2.5V
E2 E5 E7 = TURRETS_1: Component: tp; Label: GND; Manufacturer: Keystone; Manufacturer P/N: 1593-2; Vendor: Digikey; Vendor P/N: 1593-2K-ND
E3 = TURRETS_1: Component: tp; Label: VIN; Manufacturer: Keystone; Manufacturer P/N: 1593-2; Vendor: Digikey; Vendor P/N: 1593-2K-ND
E4 = TURRETS_1: Component: tp; Manufacturer: Keystone; Manufacturer P/N: 1593-2; Vendor: Digikey; Vendor P/N: 1593-2K-ND
E6 = TURRETS_1: Component: tp; Label: VOUT0_SNS; Vendor: Digikey; Vendor P/N: 1593-2K-ND
E8 = TURRETS_1: Component: tp; Label: GND0_SNS; Vendor: Digikey; Vendor P/N: 1593-2K-ND
J1 = BANANA_SMALL_0: Component: conn; Label: VIN
J2 J4 J6 = BANANA_SMALL_0: Component: conn; Label: GND
J3 = BANANA_SMALL_0: Component: conn; Label: VOUT0
P1-P25 = PAD_2: Component: tp; Label: <Label>; Vendor: Digikey; Vendor P/N: 1593-2K-ND
R1 R13 R29 R37 R57 R62 R71 R76 = RES0603_9
R2 R3 R17 R30 R31 R38 R58 R59 R63 R72 R73 R77 = RES0603_9: Manufacturer: Rohm; Manufacturer P/N: RHM0.0GCT-ND; Tolerance: 5%; Vendor: Digikey; Vendor P/N: RHM0.0GCT-ND; Volts/Amps/Watts: 0.1W
R4 R26 R32 R33 R50 R60 R74 R119 = RES0603_3
R5 R34 R61 R75 R120-R123 = RES0603_9: Label: OPT 0; Manufacturer: Rohm; Manufacturer P/N: RHM0.0GCT-ND; Vendor: Digikey
R6-R12 R15 R22 R23 R35 R36 R39 R44 R45 R64 R68 R69 R78 R82 R83 = RES0603_9: Manufacturer: ROHM; Manufacturer P/N: MCR03EZPFX1002; Vendor: Digikey; Vendor P/N: RHM10.0KHCT-ND; Volts/Amps/Watts: 0.1W
R14 R27 = RES0603_9: Component: res; Label: <label>; Manufacturer: Panasonic; Manufacturer P/N: ERJ-3EKF5901V; Tolerance: 1%; Vendor: Digikey; Vendor P/N: P5.90KHCT-ND; Volts/Amps/Watts: 0.1W
R16 R41 = RES0603_1: Manufacturer: Rohm; Manufacturer P/N: RHM0.0GCT-ND; Tolerance: 5%; Vendor: Digikey; Vendor P/N: RHM0.0GCT-ND; Volts/Amps/Watts: 0.1W
R18 = RES0603_9: Manufacturer: Rohm; Manufacturer P/N: MCR03EZPFX1000; Vendor: Digikey; Vendor P/N: RHM100HCT-ND; Volts/Amps/Watts: 0.1W
R19 R20 R40 R42 R65 R66 R79 R80 = RES0603_9: Manufacturer: Panasonic; Manufacturer P/N: ERJ-3EKF2002V; Vendor: Digikey; Vendor P/N: P20.0KHCT-ND; Volts/Amps/Watts: 0.1W
R21 R43 R67 R81 = RES0603_9: Manufacturer: Panasonic; Manufacturer P/N: ERJ-3EKF1000V; Vendor: Digikey; Vendor P/N: P100HCT-ND; Volts/Amps/Watts: 0.1W
R24 R46 R70 R84 = RES0603_9: Manufacturer: Panasonic; Manufacturer P/N: ERJ-3EKF1021V; Vendor: Digikey; Vendor P/N: P1.02KHCT-ND; Volts/Amps/Watts: 0.1W
R25 = RES0603_9: Manufacturer: Yageo; Manufacturer P/N: RC0603JR-070RL; Tolerance: 5%; Vendor: Digikey; Vendor P/N: 311-0.0GRCT-ND; Volts/Amps/Watts: 0.1W
SW1 SW2 = JP3X1_079_NO_12_3
U1-U4 = LTC3880-M0001_32: Component: IC; Manufacturer: LTC; Manufacturer P/N: LTC3880_M0001; Vendor: LTC; Vendor P/N: LTC3880_M0001
E9 = TURRETS_1: Component: tp; Label: VOUT1_SNS; Vendor: Digikey; Vendor P/N: 1593-2K-ND
E10 = TURRETS_1: Component: tp; Label: GND1_SNS; Vendor: Digikey; Vendor P/N: 1593-2K-ND
J5 = BANANA_SMALL_0: Component: conn; Label: VOUT1
R28 = RES0603_9: Label: 0; Manufacturer: Rohm; Manufacturer P/N: RHM0.0GCT-ND; Tolerance: 5%; Vendor: Digikey; Vendor P/N: RHM0.0GCT-ND; Volts/Amps/Watts: 0.1W
R47-R49 R51 R53 R54 R85 R86 R124 = RES0603_9: Label: OPT 0; Manufacturer: Rohm; Manufacturer P/N: RHM0.0GCT-ND; Tolerance: 5%; Vendor: Digikey; Vendor P/N: RHM0.0GCT-ND; Volts/Amps/Watts: 0.1W
R56 = RES0603_8
COUT24 = CAP0603_1: Component: cap; Manufacturer: TDK; Manufacturer P/N: C3225X5R0J107M; Part Type: CAP1210; Volts/Amps/Watts: 6.3v
C32 = CAP_NP: CAP, 0603 100nF 20% 16V X7R; Part Number: AVX 0603YC104MAT2A
C33 C34 = CAP_NP: CAP, 0603 10nF 10% 25V X7R; Part Number: AVX 06033C103KAT2A
D1 D2 = DIODE-LED_3: Manufacturer: PANASONIC; Manufacturer P/N: LN1371SGTRP
D3 = DIODE-LED_3: Label: GREEN; Manufacturer: PANASONIC
D4 D5 = DIODE_SCHOTTKY_9: DIODE, SCHOTTKY 30V, 100mA; Part Number: CENTRAL SEMI CMDSH-3-TR
D8 = DIODE_SCHOTTKY_0
E11 = TURRETS_2: Component: tp; Label: GPIO1B; Manufacturer: Keystone; Manufacturer P/N: 1593-2; Vendor: Digikey; Vendor P/N: 1593-2K-ND
E12 = TURRETS_2: Component: tp; Label: ALERTB; Manufacturer: Keystone; Manufacturer P/N: 1593-2; Vendor: Digikey; Vendor P/N: 1593-2K-ND
E13 = TURRETS_2: Component: tp; Label: SDA; Manufacturer: Keystone; Manufacturer P/N: 1593-2; Vendor: Digikey; Vendor P/N: 1593-2K-ND
E14 = TURRETS_2: Component: tp; Label: SCL; Manufacturer: Keystone; Manufacturer P/N: 1593-2; Vendor: Digikey; Vendor P/N: 1593-2K-ND
E15 = TURRETS_2: Component: tp; Label: SHARE_CLK; Manufacturer: Keystone; Manufacturer P/N: 1593-2; Vendor: Digikey; Vendor P/N: 1593-2K-ND
E16 = TURRETS_2: Component: tp; Label: SYNC; Manufacturer: Keystone; Manufacturer P/N: 1593-2; Vendor: Digikey; Vendor P/N: 1593-2K-ND
E17 E22 = TURRETS_2: Component: tp; Label: GND; Manufacturer: Keystone; Manufacturer P/N: 1593-2; Vendor: Digikey; Vendor P/N: 1593-2K-ND
E18 = TURRETS_2: Component: tp; Label: GPIO0B; Manufacturer: Keystone; Manufacturer P/N: 1593-2; Vendor: Digikey; Vendor P/N: 1593-2K-ND
E19 = TURRETS_2: Component: tp; Label: RUN0; Manufacturer: Keystone; Manufacturer P/N: 1593-2; Vendor: Digikey; Vendor P/N: 1593-2K-ND
E21 = TURRETS_2: Component: tp; Label: RUN1; Manufacturer: Keystone; Manufacturer P/N: 1593-2; Vendor: Digikey; Vendor P/N: 1593-2K-ND
E25 = E_0: TURRET; Part Number: MILL MAX 2501-2-00-80-00-00-07-0
J7 = HD2X6-079-PMBUS_2: HEADER, 12PIN 2mm STR DL; Label: DC1427A HEADER; Manufacturer: MOLEX; Manufacturer P/N: 87831-1220; Part Number: FCI 98414-G06-12ULF; Type: header 12POS 2MM VERT; Vendor: Digikey; Vendor P/N: WM18561-ND
J12 = PMBUS_HEADER20_3: HEADER, 20PIN DUAL ROW R/A; Component: con; Manufacturer: Mill Max; Manufacturer P/N: 802-40-020-20-0001; Part Number: MILL MAX 802-40-020-20-0001; Type: header RA 20 dual row; Vendor: LTC; Vendor P/N: 802-40-020-20-001
J13 = PMBUS_CONNECTOR20_3: CONN, SOCKET 20PIN  DUAL ROW R/A; Component: con; Manufacturer: Mill Max; Manufacturer P/N: 803-93-020-20-001; Part Number: MILL MAX 803-93-020-20-001; Type: conn  RA 20 dual row; Vendor: LTC; Vendor P/N: 803-93-020-20-001
J14 = HD2X6-079-PMBUS_4: HEADER, 4PIN 2mm STR DL; Manufacturer: Hirose; Type: header 4POS 2MM VERT
Q2 = P-MOSFET: XSTR, N-CHANNEL DMOS FET
Q3 = TRANSISTOR_0: XSTR, N-CHANNEL DMOS FET
Q4 = TRANSISTOR_1: XSTR, N-CHANNEL DMOS FET
Q19 = P-MOSFET: XSTR, N-CHANNEL DMOS FET; Part Number: VISHAY TP0101K-T1-E3
R125 R129 = RES0603_1: RES, 0603 10 OHMS 5% 1/10W; Manufacturer: Rohm; Manufacturer P/N: RHM0.0GCT-ND; Part Number: VISHAY CRCW060310R0JNEA; Tolerance: 5%; Vendor: Digikey; Vendor P/N: RHM0.0GCT-ND; Volts/Amps/Watts: 0.1W
R126 R132 R133 R137 R139 R140 R142 = RES0603_0: RES, 0603 OPTION; Label: OPT 0; Manufacturer: Rohm; Manufacturer P/N: RHM0.0GCT-ND; Part Number: OPTION; Tolerance: 5%; Vendor: Digikey; Vendor P/N: RHM0.0GCT-ND; Volts/Amps/Watts: 0.1W
R127 R135 R136 R143 = RES0603_0: RES, 0603 0 OHMS JUMPER; Label: OPT 0; Manufacturer: Rohm; Manufacturer P/N: RHM0.0GCT-ND; Part Number: VISHAY CRCW06030000Z0EA; Tolerance: 5%; Vendor: Digikey; Vendor P/N: RHM0.0GCT-ND; Volts/Amps/Watts: 0.1W
R128 R138 = RES0603_3: RES, 0603 OPTION; Label: OPT 0; Manufacturer: Rohm; Manufacturer P/N: RHM0.0GCT-ND; Part Number: OPTION; Tolerance: 5%; Vendor: Digikey; Vendor P/N: RHM0.0GCT-ND; Volts/Amps/Watts: 0.1W
R130 = RES0603_11: RES, 0603 10K OHMS 5% 1/10W; Part Number: VISHAY CRCW060310K0JNEA
R131 = RES0603_0: RES, 0603 0 OHMS JUMPER; Manufacturer: Rohm; Manufacturer P/N: RHM0.0GCT-ND; Part Number: VISHAY CRCW06030000Z0EA; Tolerance: 5%; Vendor: Digikey; Vendor P/N: RHM0.0GCT-ND; Volts/Amps/Watts: 0.1W
R134 R144 = RES0603_0: RES, 0603 4.99K OHMS 1% 1/10W; Manufacturer: ROHM; Manufacturer P/N: MCR03EZPFX4991; Part Number: VISHAY CRCW06034K99FKEA; Vendor: Digikey; Vendor P/N: RHM4.99KHCT-ND; Volts/Amps/Watts: 0.1w
R141 = RES0603_11: RES, 0603 15.8K OHMS 1% 1/10W; Part Number: VISHAY CRCW060315K8FKEA
U9 = 24LC025-I_SN: IC, 24LC05-I/ST; Part Number: MICROCHIP 24LC025-I/ST
C64 = CAP1206_1: Manufacturer: AVX; Tolerance: 10%; Type: cer 1206 X7R; Vendor: Digikey; Vendor P/N: 478-1567-1-ND; Volts/Amps/Watts: 25V
C65 C67 C68 = CAP1206_1: Manufacturer: AVX; Manufacturer P/N: 12063C105KAT2A; Tolerance: 10%; Type: cer 1206 X7R; Vendor: Digikey; Vendor P/N: 478-1567-1-ND; Volts/Amps/Watts: 25V
C66 = CAP1206_1: Manufacturer: Kemet; Manufacturer P/N: C1206C106K8RACTU; Tolerance: 10%; Type: cer 1206 X7R; Vendor: Digikey; Vendor P/N: 399-4937-1-ND; Volts/Amps/Watts: 10V
C70 = CAP_NP_1: CAP, 0603 1.5nF 10% 50V X7R; Part Number: AVX 06033C152KAT
E23 = TURRETS_2: Label: EXT PULSE; Manufacturer: Keystone; Manufacturer P/N: 1593-2; Vendor: Digikey; Vendor P/N: 1593-2K-ND
E24 = TURRETS_2: Label: GND; Manufacturer: Keystone; Manufacturer P/N: 1593-2; Vendor: Digikey; Vendor P/N: 1593-2K-ND
J10 J11 = BNC5-SCH_0: CONN,BNC,5 PINS; Part Number: CONNEX 112404
JP1 JP2 = JP3X1_079_NO_12_2
Q11 Q12 = SUND50N03: XSTR, N-CHANNEL DMOS FET; 5TH PART FIELD: 2N7002TA
R102 = RES0603_5: Label: 1W; Manufacturer: VISHAY; Manufacturer P/N: CRCW251230R0JNEG; Tolerance: 5%; Vendor: Digikey; Vendor P/N: 541-30XCT-ND; Volts/Amps/Watts: 0.1W
R103 = RES0603_6: Label: 1W; Tolerance: 5%; Vendor: Digikey; Vendor P/N: 541-30XCT-ND; Volts/Amps/Watts: 0.1W
R104-R107 R111-R117 = RES0603_9: Manufacturer: ROHM; Manufacturer P/N: MCR03EZPFX4991; Vendor: Digikey; Vendor P/N: RHM4.99KHCT-ND; Volts/Amps/Watts: 0.1w
R108 R118 = RES0603_5: Label: 1W; Manufacturer: VISHAY; Manufacturer P/N: CRCW251230R0JNEG; Part Type: 2512; Tolerance: 5%; Vendor: Digikey; Vendor P/N: 541-30XCT-ND; Volts/Amps/Watts: 0.1W
R109 = RES0603_11
R110 = POT_A_0
U6 = LT1129CS8-3.3
U7 = LT1129CS8-3_0.3
U8 = LT1129CS8-3_3.3

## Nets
3V3: J7.5(LGKPWR) Q2.2(S) Q19.3(D) R85.1 R124.1 R142.1
+5V: C64.2 C68.1 R104.2 R123.1 U6.1(OUTPUT) U6.2(SENSE/ADJ)
GND_POWER: C32.2 C33.2 C34.2 C64.1 C65.2 C66.2 C70.1 CIN1.2 CIN2.2 CIN3.2 CIN4.2 CIN5.2 CIN6.2 CIN7.2 CIN8.2 CIN9.2 CIN10.2 CIN11.2 CIN12.2 CIN13.2 CIN14.2 CIN15.2 CIN16.2 CIN17.2 CIN18.2 CIN19.2 COUT1.2 COUT2.2 COUT3.2 COUT4.2 COUT5.2 COUT6.2 COUT7.2 COUT8.2 COUT9.2 COUT10.2 COUT11.2 COUT12.2 COUT13.2 COUT14.2 COUT15.2 COUT16.2 COUT17.2 COUT18.2 COUT19.2 COUT20.2 COUT21.2 COUT22.2 COUT23.2 COUT24.2 COUT25.2 COUT26.2 COUT27.2 COUT28.2 COUT29.2 COUT30.2 COUT31.2 COUT32.2 COUT33.2 COUT34.2 COUT35.2 COUT36.2 COUT37.2 COUT38.2 COUT39.2 COUT40.2 COUT41.2 COUT42.2 COUT43.2 COUT44.2 COUT45.2 COUT46.2 E4.1(TP) E24.1(TP) J2.1(TP) J4.1(TP) J6.1(TP) J7.3(GND) J7.10(GND) J10.2 J10.3 J10.4 J10.5 J11.2 J11.3 J11.4 J11.5 J12.11(GND) J12.12(GND) J13.11(GND) J13.12(GND) J14.2(GND) JP1.1 R1.2 R13.2 R25.2 R26.1 R29.2 R33.2 R37.2 R57.2 R62.2 R71.2 R76.2 R102.1 R103.1 R108.1 R116.2 R118.1 R141.2 U1.A4(GND) U1.A6(GND) U1.A7(GND) U1.A8(GND) U1.A9(GND) U1.A10(GND) U1.B4(GND) U1.B5(GND) U1.B6(GND) U1.B7(GND) U1.B8(GND) U1.B9(GND) U1.C4(GND) U1.C6(GND) U1.C7(GND) U1.C8(GND) U1.C9(GND) U1.D4(GND) U1.D7(GND) U1.E3(GND) U1.F3(GND) U1.F10(GND) U1.G3(GND) U1.G10(GND) U1.G11(GND) U1.G12(GND) U1.H3(GND) U1.H10(GND) U1.J4(GND) U1.J10(GND) U1.K4(GND) U1.K7(GND) U1.K8(GND) U1.K9(GND) U1.L4(GND) U1.L5(GND) U1.L6(GND) U1.L7(GND) U1.L8(GND) U1.L9(GND) U1.M4(GND) U1.M6(GND) U1.M7(GND) U1.M8(GND) U1.M9(GND) U1.M10(GND) U2.A4(GND) U2.A6(GND) U2.A7(GND) U2.A8(GND) U2.A9(GND) U2.A10(GND) U2.B4(GND) U2.B5(GND) U2.B6(GND) U2.B7(GND) U2.B8(GND) U2.B9(GND) U2.C4(GND) U2.C6(GND) U2.C7(GND) U2.C8(GND) U2.C9(GND) U2.D4(GND) U2.D7(GND) U2.E3(GND) U2.F3(GND) U2.F10(GND) U2.G3(GND) U2.G10(GND) U2.G11(GND) U2.G12(GND) U2.H3(GND) U2.H10(GND) U2.J4(GND) U2.J10(GND) U2.K4(GND) U2.K7(GND) U2.K8(GND) U2.K9(GND) U2.L4(GND) U2.L5(GND) U2.L6(GND) U2.L7(GND) U2.L8(GND) U2.L9(GND) U2.M4(GND) U2.M6(GND) U2.M7(GND) U2.M8(GND) U2.M9(GND) U2.M10(GND) U3.A4(GND) U3.A6(GND) U3.A7(GND) U3.A8(GND) U3.A9(GND) U3.A10(GND) U3.B4(GND) U3.B5(GND) U3.B6(GND) U3.B7(GND) U3.B8(GND) U3.B9(GND) U3.C4(GND) U3.C6(GND) U3.C7(GND) U3.C8(GND) U3.C9(GND) U3.D4(GND) U3.D7(GND) U3.E3(GND) U3.F3(GND) U3.F10(GND) U3.G3(GND) U3.G10(GND) U3.G11(GND) U3.G12(GND) U3.H3(GND) U3.H10(GND) U3.J4(GND) U3.J10(GND) U3.K4(GND) U3.K7(GND) U3.K8(GND) U3.K9(GND) U3.L4(GND) U3.L5(GND) U3.L6(GND) U3.L7(GND) U3.L8(GND) U3.L9(GND) U3.M4(GND) U3.M6(GND) U3.M7(GND) U3.M8(GND) U3.M9(GND) U3.M10(GND) U4.A4(GND) U4.A6(GND) U4.A7(GND) U4.A8(GND) U4.A9(GND) U4.A10(GND) U4.B4(GND) U4.B5(GND) U4.B6(GND) U4.B7(GND) U4.B8(GND) U4.B9(GND) U4.C4(GND) U4.C6(GND) U4.C7(GND) U4.C8(GND) U4.C9(GND) U4.D4(GND) U4.D7(GND) U4.E3(GND) U4.F3(GND) U4.F10(GND) U4.G3(GND) U4.G10(GND) U4.G11(GND) U4.G12(GND) U4.H3(GND) U4.H10(GND) U4.J4(GND) U4.J10(GND) U4.K4(GND) U4.K7(GND) U4.K8(GND) U4.K9(GND) U4.L4(GND) U4.L5(GND) U4.L6(GND) U4.L7(GND) U4.L8(GND) U4.L9(GND) U4.M4(GND) U4.M6(GND) U4.M7(GND) U4.M8(GND) U4.M9(GND) U4.M10(GND) U6.3(GND) U6.6(GND) U6.7(GND) U9.1(A0) U9.2(A1) U9.3(A2) U9.4(VSS) U9.7(WP)
GND_SIGNAL: C1.2 C2.2 C3.2 C5.2 C8.2 C9.2 C10.2 C12.2 C13.2 C14.2 C15.2 C17.2 C18.2 C19.2 C67.2 C68.2 E10.1(TP) E17.1(TP) E22.1(TP) Q3.2(S) Q4.2(S) R14.2 R15.1 R19.1 R20.1 R21.1 R22.1 R23.1 R24.1 R26.2 R27.2 R33.1 R39.1 R40.1 R42.1 R43.1 R44.1 R45.1 R46.1 R64.1 R65.1 R66.1 R67.1 R68.1 R69.1 R70.1 R78.1 R79.1 R80.1 R81.1 R82.1 R83.1 R84.1 R86.2 R105.2 R110.1 R110.2 R113.2 R115.2 R119.1 SW1.3 SW2.3 U1.F7(SGND) U1.F8(SGND) U1.G7(SGND) U1.G8(SGND) U2.F7(SGND) U2.F8(SGND) U2.G7(SGND) U2.G8(SGND) U3.F7(SGND) U3.F8(SGND) U3.G7(SGND) U3.G8(SGND) U4.F7(SGND) U4.F8(SGND) U4.G7(SGND) U4.G8(SGND) U7.2(GND) U8.2(V-)
VDD33: D8.1(CATHODE) Q19.2(S)
VIN: C65.1 CIN1.1 CIN2.1 CIN3.1 CIN4.1 CIN5.1 CIN6.1 CIN7.1 CIN8.1 CIN9.1 CIN10.1 CIN11.1 CIN12.1 CIN13.1 CIN14.1 CIN15.1 CIN16.1 CIN17.1 CIN18.1 CIN19.1 E3.1(TP) J1.1(TP) R4.1 R5.1 R32.1 R34.1 R60.1 R61.1 R74.1 R75.1 R109.1 R130.1 R138.1 U1.A11(VINH0) U1.A12(VINH0) U1.B11(VINH0) U1.B12(VINH0) U1.C11(VINH0) U1.C12(VINH0) U1.D11(VINH0) U1.D12(VINH0) U1.E12(VINH0) U1.H12(VINH1) U1.J11(VINH1) U1.J12(VINH1) U1.K11(VINH1) U1.K12(VINH1) U1.L11(VINH1) U1.L12(VINH1) U1.M11(VINH1) U1.M12(VINH1) U2.A11(VINH0) U2.A12(VINH0) U2.B11(VINH0) U2.B12(VINH0) U2.C11(VINH0) U2.C12(VINH0) U2.D11(VINH0) U2.D12(VINH0) U2.E12(VINH0) U2.H12(VINH1) U2.J11(VINH1) U2.J12(VINH1) U2.K11(VINH1) U2.K12(VINH1) U2.L11(VINH1) U2.L12(VINH1) U2.M11(VINH1) U2.M12(VINH1) U3.A11(VINH0) U3.A12(VINH0) U3.B11(VINH0) U3.B12(VINH0) U3.C11(VINH0) U3.C12(VINH0) U3.D11(VINH0) U3.D12(VINH0) U3.E12(VINH0) U3.H12(VINH1) U3.J11(VINH1) U3.J12(VINH1) U3.K11(VINH1) U3.K12(VINH1) U3.L11(VINH1) U3.L12(VINH1) U3.M11(VINH1) U3.M12(VINH1) U4.A11(VINH0) U4.A12(VINH0) U4.B11(VINH0) U4.B12(VINH0) U4.C11(VINH0) U4.C12(VINH0) U4.D11(VINH0) U4.D12(VINH0) U4.E12(VINH0) U4.H12(VINH1) U4.J11(VINH1) U4.J12(VINH1) U4.K11(VINH1) U4.K12(VINH1) U4.L11(VINH1) U4.L12(VINH1) U4.M11(VINH1) U4.M12(VINH1) U6.8(VIN)
ALERTB: E12.1(TP) J7.6(ALERTB) J12.3(ALERTB) J13.3(ALERTB) Q2.1(G) R8.2 U1.E5(~{ALERT}) U2.E5(~{ALERT}) U3.E5(~{ALERT}) U4.E5(~{ALERT})
AUX3V4: D8.2(ANODE) J14.4(AUX3V4)
AUXVCC: C32.1 E25.1(A) J7.1(AUXP) J12.8(AUXP) J13.8(AUXP) R134.1 R144.1 U9.8(VCC)
COMP0: C1.1 C3.1 C4.1 C10.1 C13.1 C15.1 C17.1 C19.1 R3.2 R17.1 R38.1 R50.1 R59.2 R63.1 R73.2 R77.1 U1.E8(COMP0a) U1.H8(COMP1a) U2.E8(COMP0a) U3.E8(COMP0a) U3.H8(COMP1a) U4.E8(COMP0a) U4.H8(COMP1a)
COMP1: C7.1 C8.1 R31.2 R50.2 U2.H8(COMP1a)
EESCL: J7.11(AUXSCL) R134.2 U9.6(SCL)
EESDA: J7.12(AUXSDA) R144.2 U9.5(SDA)
GPIO0B: D5.2(ANODE) E18.1(TP) Q3.1(G) R11.2 R47.2 R120.1 R121.1 R122.1 R126.2 R135.2 U1.E4(~{GPIO0}) U2.E4(~{GPIO0}) U3.E4(~{GPIO0}) U4.E4(~{GPIO0})
GPIO1B: D4.2(ANODE) E11.1(TP) Q4.1(G) R35.2 R47.1 R133.2 R136.2 U2.F4(~{GPIO1})
RUN0: D5.1(CATHODE) E19.1(TP) R12.2 R16.2 R48.2 R125.2 R133.1 R139.2 R143.2 SW1.1 SW1.2 U1.F5(RUN0) U1.F6(RUN1) U2.F5(RUN0) U3.F5(RUN0) U3.F6(RUN1) U4.F5(RUN0) U4.F6(RUN1)
RUN1: D4.1(CATHODE) E21.1(TP) R36.2 R41.2 R48.1 R126.1 R127.2 R129.2 R132.2 SW2.1 SW2.2 U2.F6(RUN1)
SCL: E14.1(TP) J7.4(SCL) J12.6(SCL) J13.6(SCL) J14.3(SCL) R9.2 U1.E6(SCL) U2.E6(SCL) U3.E6(SCL) U4.E6(SCL)
SDA: E13.1(TP) J7.2(SDA) J12.4(SDA) J13.4(SDA) J14.1(SDA) R10.2 U1.D6(SDA) U2.D6(SDA) U3.D6(SDA) U4.D6(SDA)
SHARE_CLK: E15.1(TP) R7.2 R131.1 U1.H7(SHARE_CLK) U2.H7(SHARE_CLK) U3.H7(SHARE_CLK) U4.H7(SHARE_CLK)
SYNC: E16.1(TP) R6.2 R140.1 U1.E7(SYNC) U2.E7(SYNC) U3.E7(SYNC) U4.E7(SYNC)
VOSNS0+: C2.1 C6.1 C11.1 C14.1 C16.1 C18.1 C20.1 E6.1(TP) R18.1 R56.1 U1.D9(VOSNS0+) U1.H9(VOSNS1) U2.D9(VOSNS0+) U3.D9(VOSNS0+) U3.H9(VOSNS1) U4.D9(VOSNS0+) U4.H9(VOSNS1)
VOSNS0-: C6.2 C11.2 C16.2 C20.2 E8.1(TP) R25.1 R119.2 U1.E9(VOSNS0-) U2.E9(VOSNS0-) U3.E9(VOSNS0-) U4.E9(VOSNS0-)
VOSNS1: C9.1 E9.1(TP) R28.2 R56.2 U2.H9(VOSNS1)
VOUT0: C66.1 COUT1.1 COUT2.1 COUT3.1 COUT4.1 COUT5.1 COUT6.1 COUT7.1 COUT8.1 COUT9.1 COUT10.1 COUT11.1 COUT19.1 COUT20.1 COUT21.1 COUT22.1 COUT23.1 COUT24.1 COUT25.1 COUT26.1 COUT27.1 COUT28.1 COUT29.1 COUT30.1 COUT31.1 COUT32.1 COUT33.1 COUT34.1 COUT35.1 COUT36.1 COUT37.1 COUT38.1 COUT39.1 COUT40.1 COUT41.1 COUT42.1 COUT43.1 COUT45.1 COUT46.1 J3.1(TP) J11.1 Q11.3 Q12.3 R18.2 R49.2 R51.2 R53.2 R54.2 R102.2 U1.A1(VOUT0) U1.A2(VOUT0) U1.A3(VOUT0) U1.B1(VOUT0) U1.B2(VOUT0) U1.B3(VOUT0) U1.C1(VOUT0) U1.C2(VOUT0) U1.C3(VOUT0) U1.D1(VOUT0) U1.D2(VOUT0) U1.D3(VOUT0) U1.J1(VOUT1) U1.J2(VOUT1) U1.J3(VOUT1) U1.K1(VOUT1) U1.K2(VOUT1) U1.K3(VOUT1) U1.L1(VOUT1) U1.L2(VOUT1) U1.L3(VOUT1) U1.M1(VOUT1) U1.M2(VOUT1) U1.M3(VOUT1) U2.A1(VOUT0) U2.A2(VOUT0) U2.A3(VOUT0) U2.B1(VOUT0) U2.B2(VOUT0) U2.B3(VOUT0) U2.C1(VOUT0) U2.C2(VOUT0) U2.C3(VOUT0) U2.D1(VOUT0) U2.D2(VOUT0) U2.D3(VOUT0) U3.A1(VOUT0) U3.A2(VOUT0) U3.A3(VOUT0) U3.B1(VOUT0) U3.B2(VOUT0) U3.B3(VOUT0) U3.C1(VOUT0) U3.C2(VOUT0) U3.C3(VOUT0) U3.D1(VOUT0) U3.D2(VOUT0) U3.D3(VOUT0) U3.J1(VOUT1) U3.J2(VOUT1) U3.J3(VOUT1) U3.K1(VOUT1) U3.K2(VOUT1) U3.K3(VOUT1) U3.L1(VOUT1) U3.L2(VOUT1) U3.L3(VOUT1) U3.M1(VOUT1) U3.M2(VOUT1) U3.M3(VOUT1) U4.A1(VOUT0) U4.A2(VOUT0) U4.A3(VOUT0) U4.B1(VOUT0) U4.B2(VOUT0) U4.B3(VOUT0) U4.C1(VOUT0) U4.C2(VOUT0) U4.C3(VOUT0) U4.D1(VOUT0) U4.D2(VOUT0) U4.D3(VOUT0) U4.J1(VOUT1) U4.J2(VOUT1) U4.J3(VOUT1) U4.K1(VOUT1) U4.K2(VOUT1) U4.K3(VOUT1) U4.L1(VOUT1) U4.L2(VOUT1) U4.L3(VOUT1) U4.M1(VOUT1) U4.M2(VOUT1) U4.M3(VOUT1)
VOUT1: COUT12.1 COUT13.1 COUT14.1 COUT15.1 COUT16.1 COUT17.1 COUT18.1 COUT44.1 J5.1(TP) R28.1 R49.1 R51.1 R53.1 R54.1 R103.2 U2.J1(VOUT1) U2.J2(VOUT1) U2.J3(VOUT1) U2.K1(VOUT1) U2.K2(VOUT1) U2.K3(VOUT1) U2.L1(VOUT1) U2.L2(VOUT1) U2.L3(VOUT1) U2.M1(VOUT1) U2.M2(VOUT1) U2.M3(VOUT1)
N23048166: R2.2 U1.K5(TSNS1b)
N23048182: R17.2 U1.D8(COMP0b)
N23048213: E2.1(TP) R5.2 U1.F9(INTVCC) U1.G9(INTVCC)
N23048244: E7.1(TP) U1.J6(VDD25)
N23048252: U1.H1(ISNS1b+) U1.H2(ISNS1a+)
N23048279: U1.C5(TSNS0b) U1.D5(TSNS0a)
N23048281: U1.G1(ISNS1b-) U1.G2(ISNS1a-)
N23048321: U1.F1(ISNS0b+) U1.F2(ISNS0a+)
N23048372: U1.E1(ISNS0b-) U1.E2(ISNS0a-)
N23048626: P3.1(TP) U1.B10(SW0)
N23048647: R13.1 U1.A5(SNUB0)
N23048689: R3.1 U1.J8(COMP1b)
N23048718: R15.2 U1.K6(WP)
N23048904: R1.1 U1.M5(SNUB1)
N23048908: E5.1(TP) R6.1 R7.1 R8.1 R9.1 R10.1 R11.1 R12.1 U1.J7(VDD33)
N23049063: C4.2 R14.1
N23049093: R120.2 U1.F4(~{GPIO1})
N23049125: R19.2 U1.G4(ASEL)
N23049166: R20.2 U1.H4(FSWPHCFG)
N23049241: R21.2 U1.G5(VOUT0CFG)
N23049288: R22.2 U1.H5(VTRIM0CFG)
N23049318: P2.1(TP) U1.J9(VORB1)
N23049332: C5.1 R16.1
N23049399: R23.2 U1.G6(VOUT1CFG)
N23049449: P4.1(TP) U1.D10(VORB0+)
N23049466: R24.2 U1.H6(VTRIM1CFG)
N23049468: R4.2 U1.F11(VINL) U1.F12(VINL)
N23049481: P5.1(TP) U1.E10(VORB0-)
N23049661: R2.1 U1.J5(TSNS1a)
N23052161: R35.1 R36.1 U2.J7(VDD33)
N23052201: C12.1 R41.1
N23052277: R30.2 U2.K5(TSNS1b)
N23052291: R38.2 U2.D8(COMP0b)
N23052340: R34.2 U2.F9(INTVCC) U2.G9(INTVCC)
N23052342: U2.H1(ISNS1b+) U2.H2(ISNS1a+)
N23052360: U2.C5(TSNS0b) U2.D5(TSNS0a)
N23052362: U2.G1(ISNS1b-) U2.G2(ISNS1a-)
N23052410: U2.F1(ISNS0b+) U2.F2(ISNS0a+)
N23052469: U2.E1(ISNS0b-) U2.E2(ISNS0a-)
N23052667: P6.1(TP) U2.L10(SW1)
N23052711: P8.1(TP) U2.B10(SW0)
N23052715: R37.1 U2.A5(SNUB0)
N23052752: R31.1 U2.J8(COMP1b)
N23052761: R39.2 U2.K6(WP)
N23052850: R29.1 U2.M5(SNUB1)
N23052969: R40.2 U2.G4(ASEL)
N23053001: R42.2 U2.H4(FSWPHCFG)
N23053037: R43.2 U2.G5(VOUT0CFG)
N23053077: R44.2 U2.H5(VTRIM0CFG)
N23053100: P7.1(TP) U2.J9(VORB1)
N23053102: C7.2 R27.1
N23053122: R45.2 U2.G6(VOUT1CFG)
N23053174: P9.1(TP) U2.D10(VORB0+)
N23053186: R46.2 U2.H6(VTRIM1CFG)
N23053188: R32.2 U2.F11(VINL) U2.F12(VINL)
N23053199: P10.1(TP) U2.E10(VORB0-)
N23053400: R30.1 U2.J5(TSNS1a)
N23055509: R58.2 U3.K5(TSNS1b)
N23055523: R63.2 U3.D8(COMP0b)
N23055559: R61.2 U3.F9(INTVCC) U3.G9(INTVCC)
N23055561: U3.H1(ISNS1b+) U3.H2(ISNS1a+)
N23055565: U3.C5(TSNS0b) U3.D5(TSNS0a)
N23055567: U3.G1(ISNS1b-) U3.G2(ISNS1a-)
N23055587: U3.F1(ISNS0b+) U3.F2(ISNS0a+)
N23055658: U3.E1(ISNS0b-) U3.E2(ISNS0a-)
N23055706: P12.1(TP) U3.L10(SW1)
N23055890: P14.1(TP) U3.B10(SW0)
N23055894: R62.1 U3.A5(SNUB0)
N23055936: R59.1 U3.J8(COMP1b)
N23055938: R64.2 U3.K6(WP)
N23056021: R57.1 U3.M5(SNUB1)
N23056138: R65.2 U3.G4(ASEL)
N23056152: R121.2 U3.F4(~{GPIO1})
N23056171: R66.2 U3.H4(FSWPHCFG)
N23056210: R67.2 U3.G5(VOUT0CFG)
N23056240: R68.2 U3.H5(VTRIM0CFG)
N23056254: P13.1(TP) U3.J9(VORB1)
N23056278: R69.2 U3.G6(VOUT1CFG)
N23056328: P16.1(TP) U3.D10(VORB0+)
N23056333: R70.2 U3.H6(VTRIM1CFG)
N23056335: R60.2 U3.F11(VINL) U3.F12(VINL)
N23056344: P17.1(TP) U3.E10(VORB0-)
N23056510: R58.1 U3.J5(TSNS1a)
N23058515: R72.2 U4.K5(TSNS1b)
N23058525: R77.2 U4.D8(COMP0b)
N23058569: R75.2 U4.F9(INTVCC) U4.G9(INTVCC)
N23058571: U4.H1(ISNS1b+) U4.H2(ISNS1a+)
N23058573: U4.C5(TSNS0b) U4.D5(TSNS0a)
N23058575: U4.G1(ISNS1b-) U4.G2(ISNS1a-)
N23058587: U4.F1(ISNS0b+) U4.F2(ISNS0a+)
N23058668: U4.E1(ISNS0b-) U4.E2(ISNS0a-)
N23058716: P19.1(TP) U4.L10(SW1)
N23058896: P21.1(TP) U4.B10(SW0)
N23058904: R76.1 U4.A5(SNUB0)
N23058935: R73.1 U4.J8(COMP1b)
N23058937: R78.2 U4.K6(WP)
N23059020: R71.1 U4.M5(SNUB1)
N23059148: R79.2 U4.G4(ASEL)
N23059162: R122.2 U4.F4(~{GPIO1})
N23059181: R80.2 U4.H4(FSWPHCFG)
N23059220: R81.2 U4.G5(VOUT0CFG)
N23059250: R82.2 U4.H5(VTRIM0CFG)
N23059264: P20.1(TP) U4.J9(VORB1)
N23059288: R83.2 U4.G6(VOUT1CFG)
N23059338: P23.1(TP) U4.D10(VORB0+)
N23059343: R84.2 U4.H6(VTRIM1CFG)
N23059345: R74.2 U4.F11(VINL) U4.F12(VINL)
N23059351: P24.1(TP) U4.E10(VORB0-)
N23059512: R72.1 U4.J5(TSNS1a)
N23559214: P11.1(TP) U2.J6(VDD25)
N23584949: P15.1(TP) U3.J7(VDD33)
N23585649: P18.1(TP) U3.J6(VDD25)
N23591144: P22.1(TP) U4.J7(VDD33)
N23591838: P25.1(TP) U4.J6(VDD25)
N23744159: JP1.2 R109.2 U6.5(~{SHDN})
N23750490: JP2.2 JP2.3 Q11.1 Q12.1 R116.1 R117.2
N23750527: R105.1 R123.2 U7.4(DIV)
N23750539: C67.1 R111.1 U7.6(OUT) U8.5(V+)
N23750628: C70.2 J10.1 Q11.2 Q12.2 R107.2 R108.2 R118.2
N23750638: R104.1 U7.5(V+)
N23750777: R110.3 R112.2 R113.1
N23750815: C69.1 R106.1 U8.1(VOUT)
N23750823: R111.2 R112.1 U8.3(+IN)
N23750825: C69.2 R107.1 U8.4(-IN)
N23750915: R114.2 U7.3(SET)
N23750919: R114.1 R115.1 U7.1(MOD)
N23781336: E23.1(TP) R117.1
N23791170: JP2.1 R106.2
N24099359: P1.1(TP) U1.L10(SW1)
N24101373: D2.1(A) R124.2
N24101375: D2.2(K) Q3.3(D)
N24101381: D1.2(K) Q4.3(D)
N24101385: D3.1(A) Q2.3(D)
N24101397: D3.2(K) R86.1
N24101667: J12.1(FAULTB) J13.1(FAULTB) R132.1 R135.1 R136.1 R139.1
N24101681: J7.8(OUTEN_0) R128.1
N24101683: J7.9(OUTEN_1) R137.1
N24101695: J12.2(CTRL) J13.2(CTRL) R127.1 R128.2 R137.2 R143.1
N24101745: C33.1 R129.1
N24101747: C34.1 R125.1
N24101769: Q19.1(G) R130.2 R141.1
N24101799: J12.5(SHARE_CLK) J13.5(SHARE_CLK) R131.2
N24101801: J12.7(RESETB) J13.7(RESETB)
N24101803: J12.9(UNUSED) J13.9(UNUSED) R140.2
N24101815: J12.13(12V) J12.14(12V) J13.13(12V) J13.14(12V) R138.2
N24101887: J12.10(UNUSED) J13.10(UNUSED) R142.2
N24102650: D1.1(A) R85.2

Not connected (* = marked no-connect by the designer): J7 7(GPIO_1); JP1 3; SW1 4 5 6; SW2 4 5 6; U1 C10(DNC) E11(DNC) H11(DNC) K10(DNC); U2 C10(DNC) E11(DNC) H11(DNC) K10(DNC); U3 C10(DNC) E11(DNC) H11(DNC) K10(DNC); U4 C10(DNC) E11(DNC) H11(DNC) K10(DNC); U6 4(NC)*

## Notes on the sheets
sheet 1
- 1210
- 1210
- 1210
- 0.035 VIA
- 0805
- TESTPOINTS
- *
- 4.5V - 16V
- 35V
- 1210
- 1210
- 1210
- 1210
- 0805
- RUN0
- ON
- OFF
- 1V / 105A
- 1210
- 1210
- 1210
- NOTE: UNLESS OTHERWISE SPECIFIED
- 1.  ALL RESISTORS ARE 0603.
       ALL CAPACITORS ARE 0603.
- *
- WHEN VIN < 5.75V, SHORT INTVCC TO VIN WITH R5,R34, R61.
- µModule REGULATOR WITH DIGITAL POWER MANAGEMENT
sheet 2
- OPT
- 1210
- 1210
- 1210
- OPT
- 0.035 VIA
- 0805
- TESTPOINTS
- 1210
- 1210
- 1210
- 1210
- 0805
- RUN1
- ON
- OFF
- 1210
- 1210
- 1210
- OPTIONAL JUMPER FOR  SINGLE
  OUTPUT CONFIGURATION
- µModule REGULATOR WITH DIGITAL POWER MANAGEMENT
sheet 3
- 1210
- 1210
- 1210
- 0.035 VIA
- 0805
- TESTPOINTS
- 1210
- 1210
- 1210
- 1210
- 0805
- 1210
- 1210
- 1210
- µModule REGULATOR WITH DIGITAL POWER MANAGEMENT
sheet 4
- 1210
- 1210
- 1210
- 0.035 VIA
- 0805
- TESTPOINTS
- 1210
- 1210
- 1210
- 1210
- 0805
- µModule REGULATOR WITH DIGITAL POWER MANAGEMENT
sheet 5
- ALL PARTS ON THIS PAGE ARE FOR DEMO ONLY, NOT NEEDED IN CUSTOMER DESIGN
- TO DC2086A
- TO DC1613A
- 1206
- PSM STACKING CONNECTORS:
- OPTIONAL CIRCUIT FOR PROGRAMMING
  WITHOUT VIN
- J1, MALE, CONN  HEADER 14POS 2MM R/A GOLD, Molex Connector Corp. 87760-1416
- J2, FEMALE, CONN RECEPT 2MM DUAL R/A 14POS, Sullins Conn.
  NPPN072FJFN-RC
- GPIO1
- GPIO0
- ALERTB
- µModule REGULATOR WITH DIGITAL POWER MANAGEMENT
sheet 6
- ALL PARTS ON THIS PAGE ARE FOR DEMO ONLY, NOT NEEDED IN CUSTOMER DESIGN
- DYNAMIC LOAD CIRCUIT
- VOUT0
- PULSE
- INT
- EXT
- 70Hz, 3% Duty Cycle
- IOUT
  TST
- 0805
- 2512
- 2512
- 1%
- OPT
- OPT
- BLEEDER LOADS
- 1%
- BIAS
- ON
- OFF
- µModule REGULATOR WITH DIGITAL POWER MANAGEMENT
